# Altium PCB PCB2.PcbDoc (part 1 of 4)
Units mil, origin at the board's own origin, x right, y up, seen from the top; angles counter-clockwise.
Board outline 7170.03 x 5785.03 mil, 4 copper layers (Top Layer, GND, PWR, Bottom Layer), stack 22.378 mil thick; 348 components, 320 nets, 1937 pads, 429 vias.
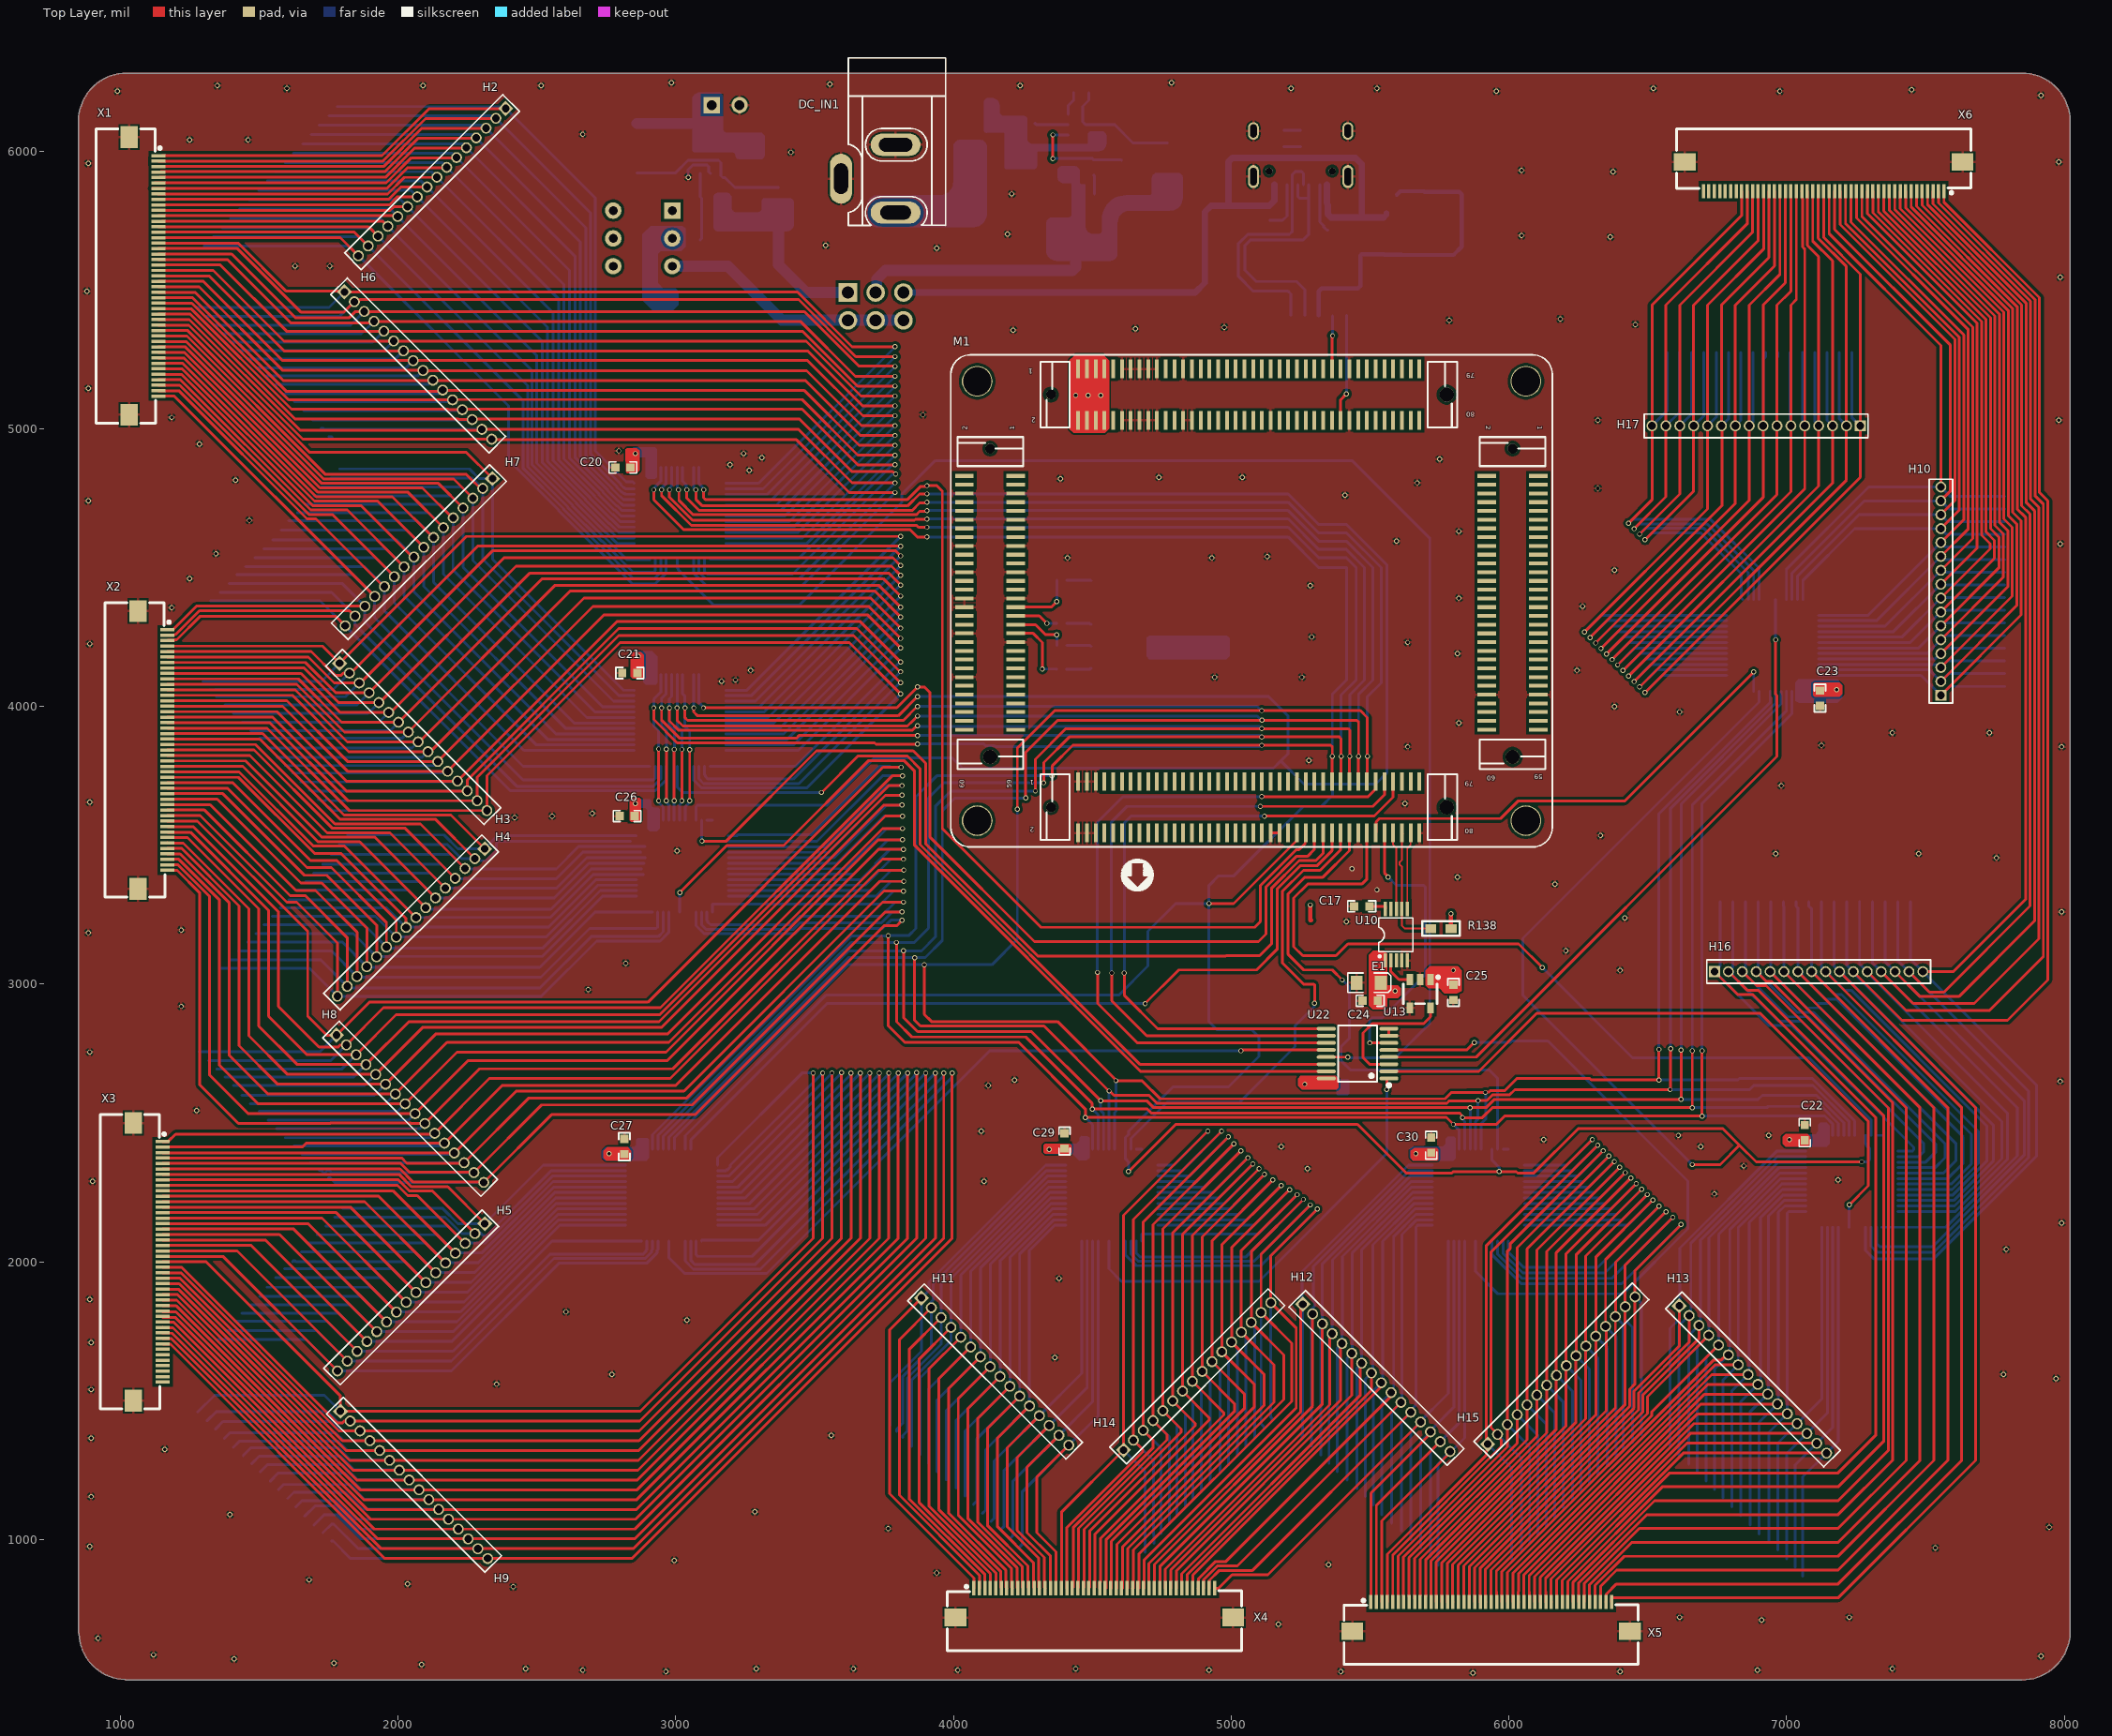
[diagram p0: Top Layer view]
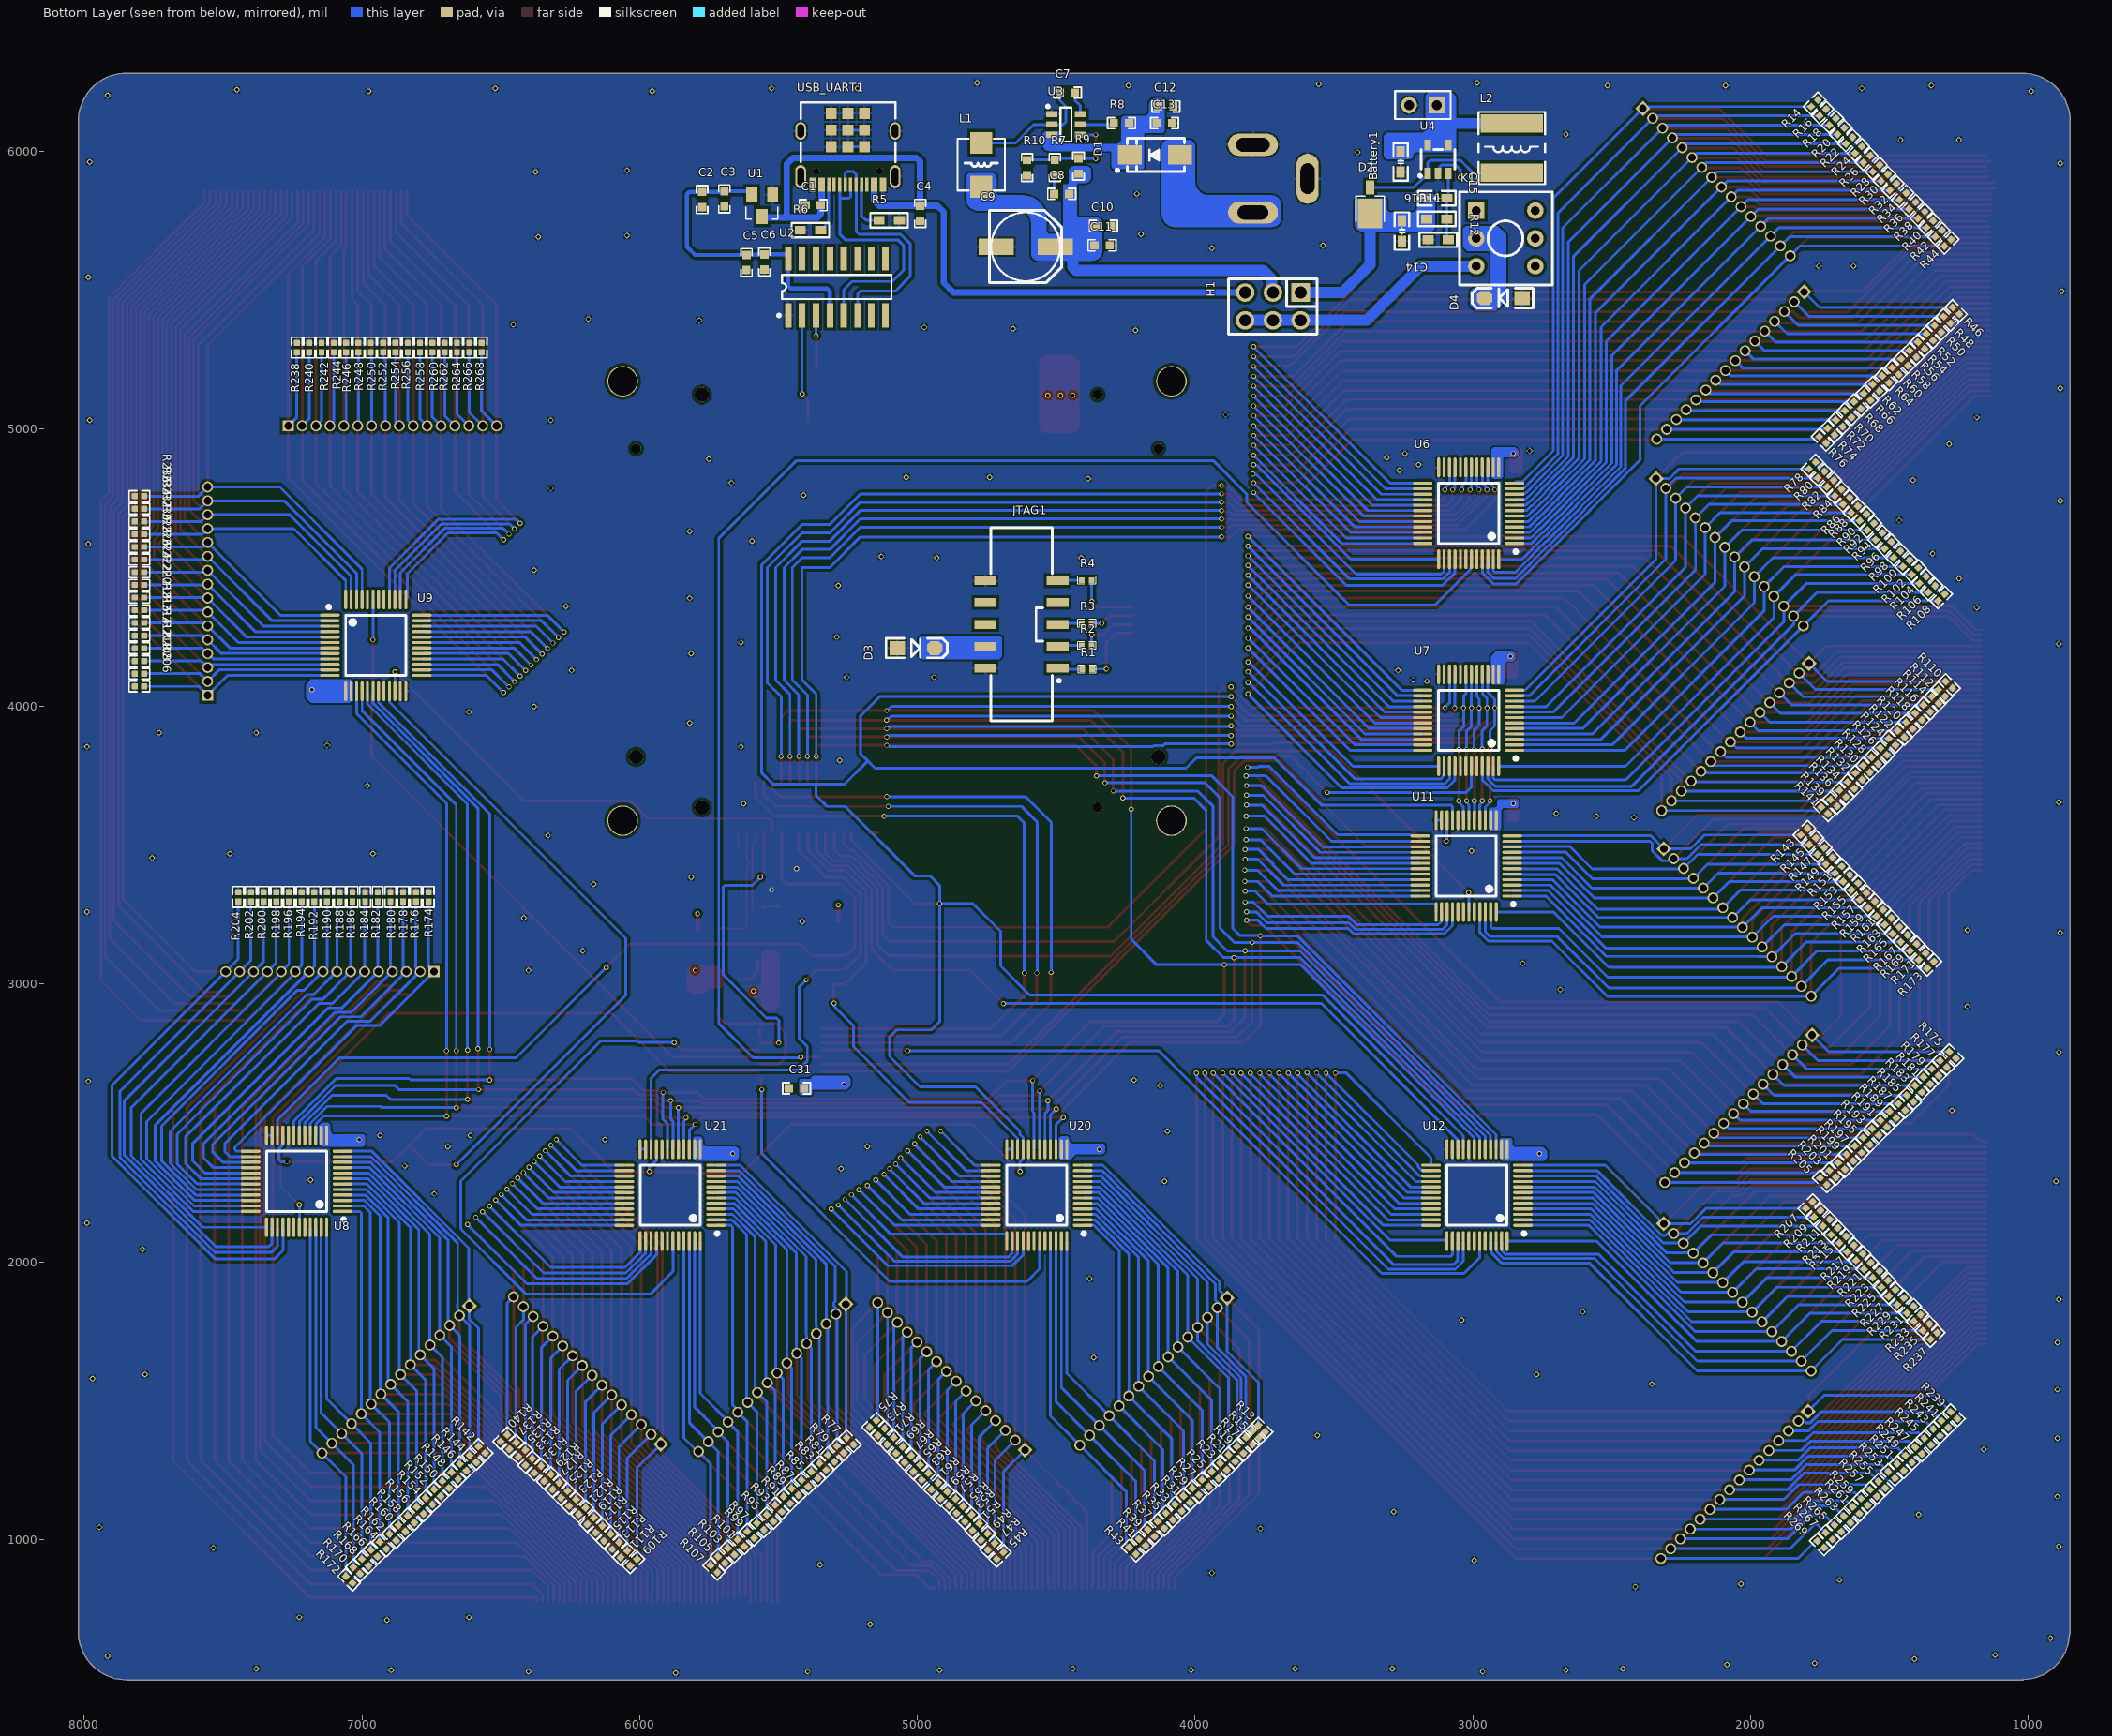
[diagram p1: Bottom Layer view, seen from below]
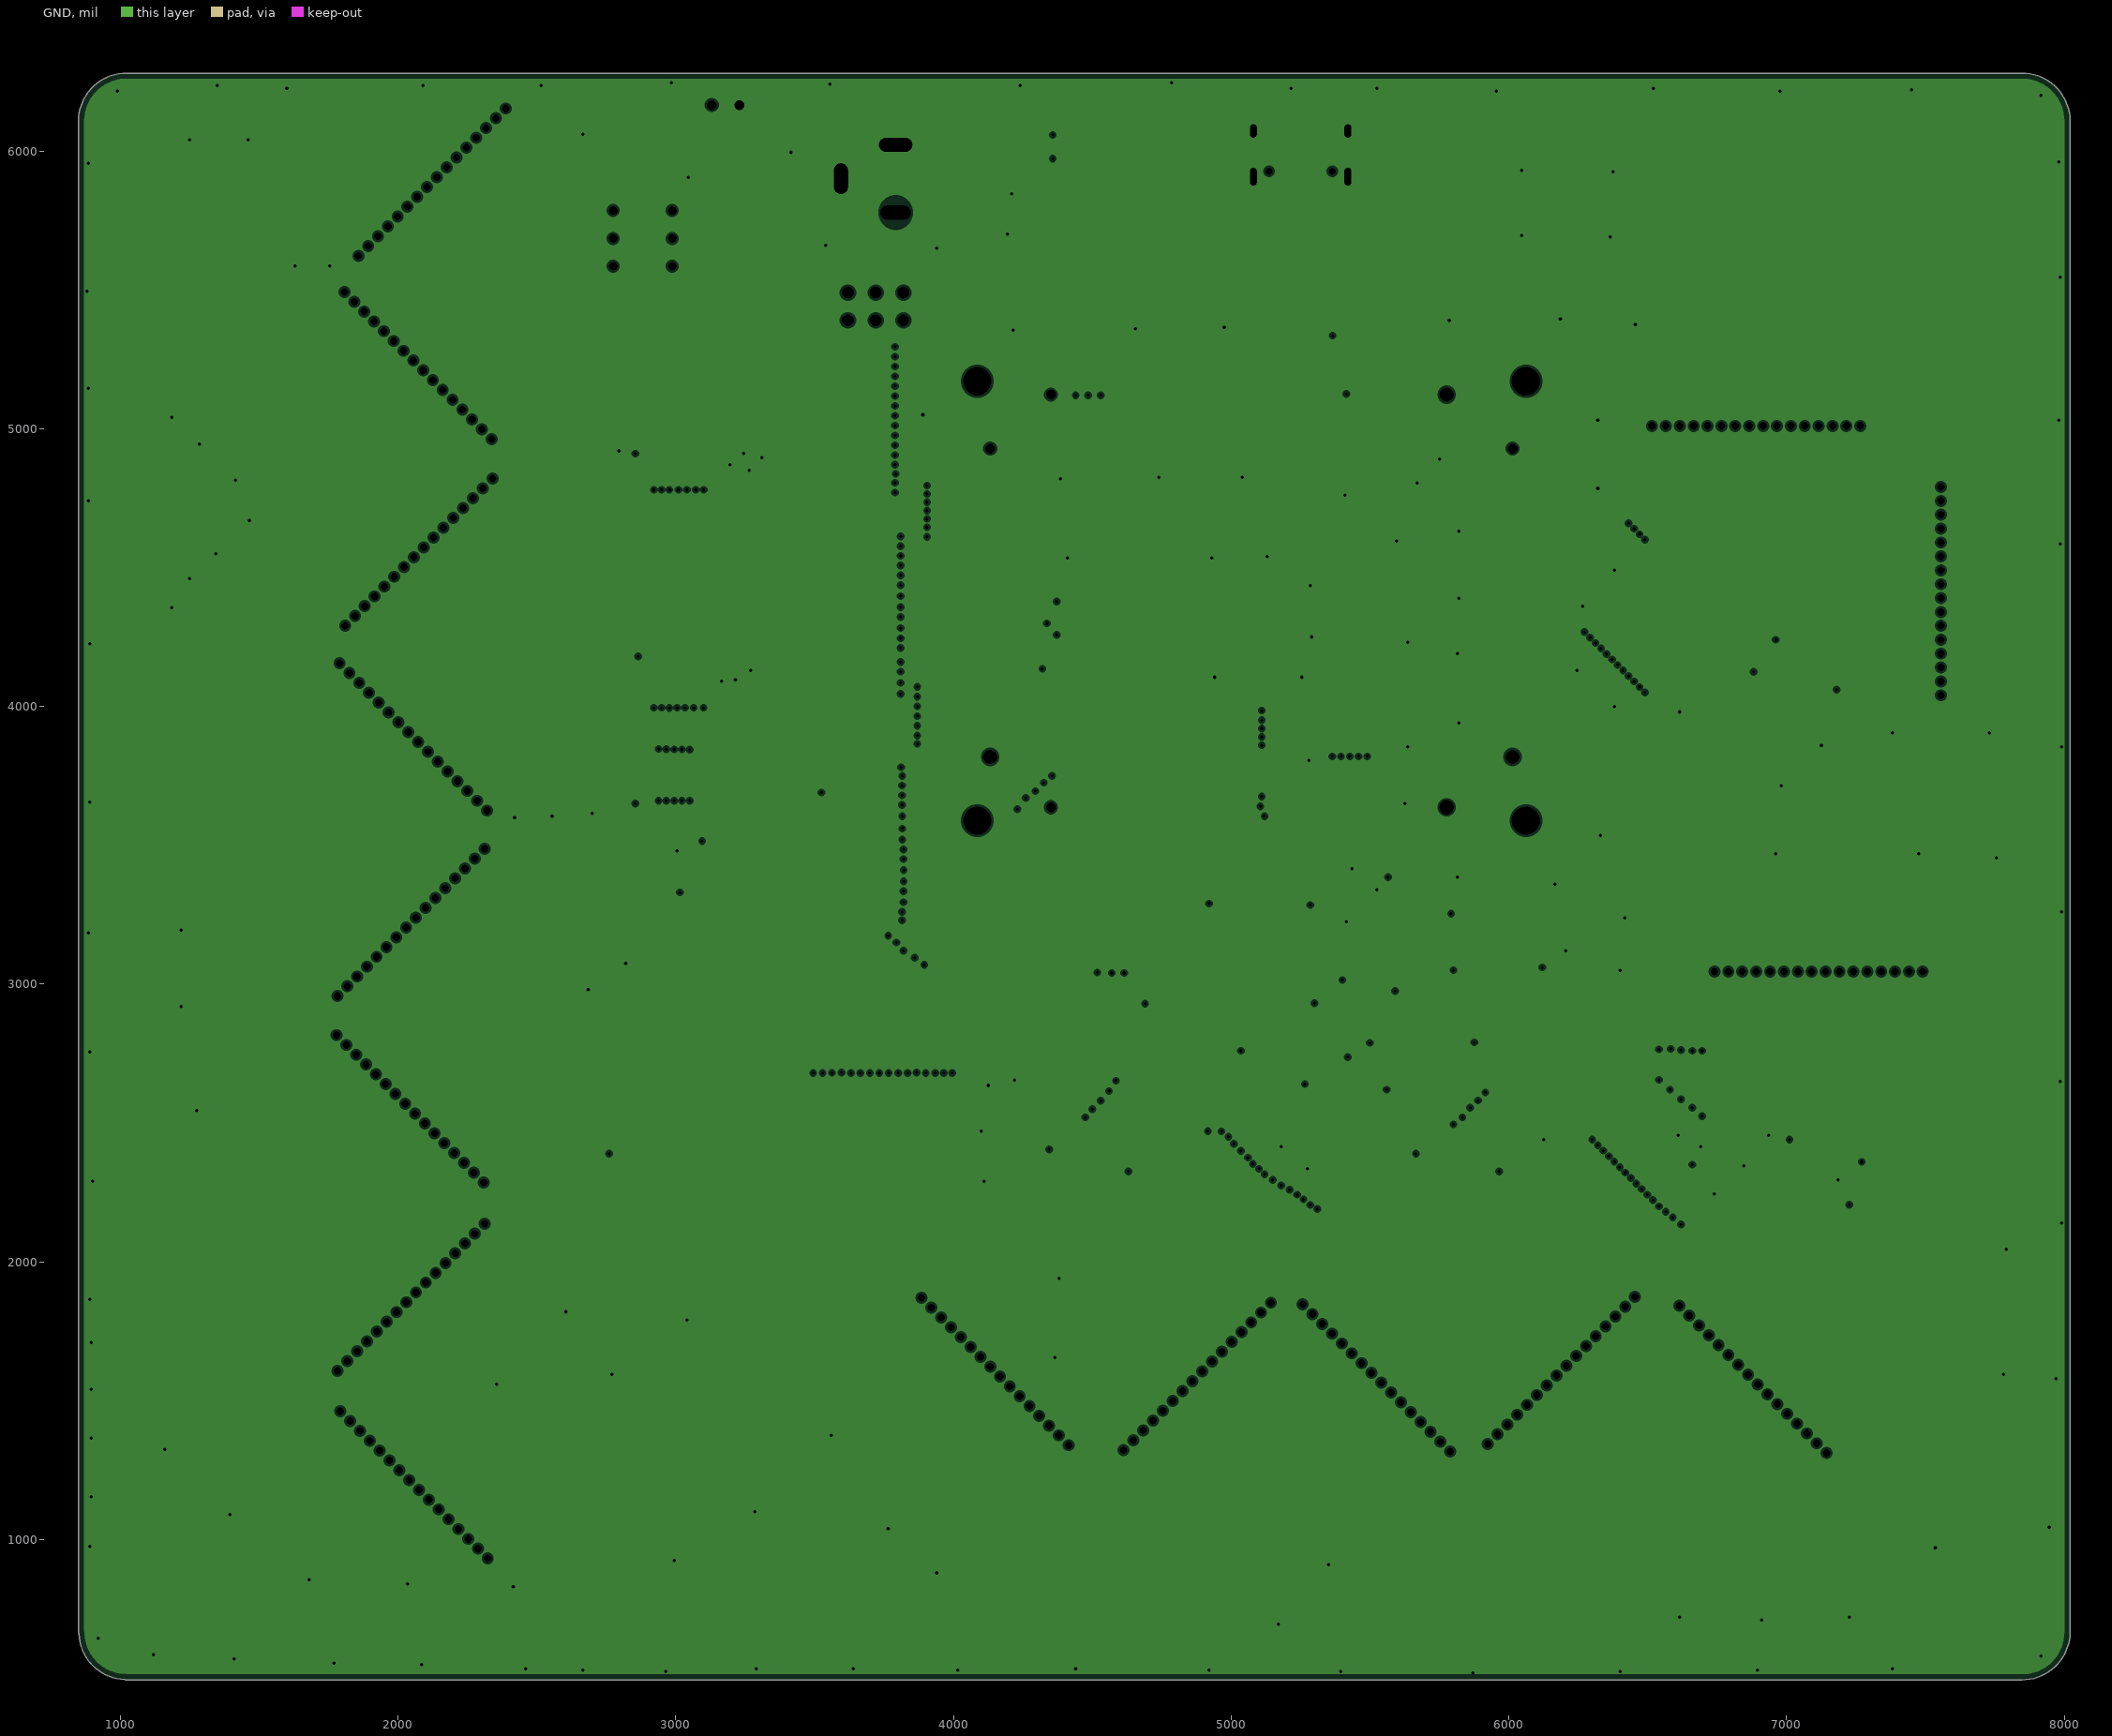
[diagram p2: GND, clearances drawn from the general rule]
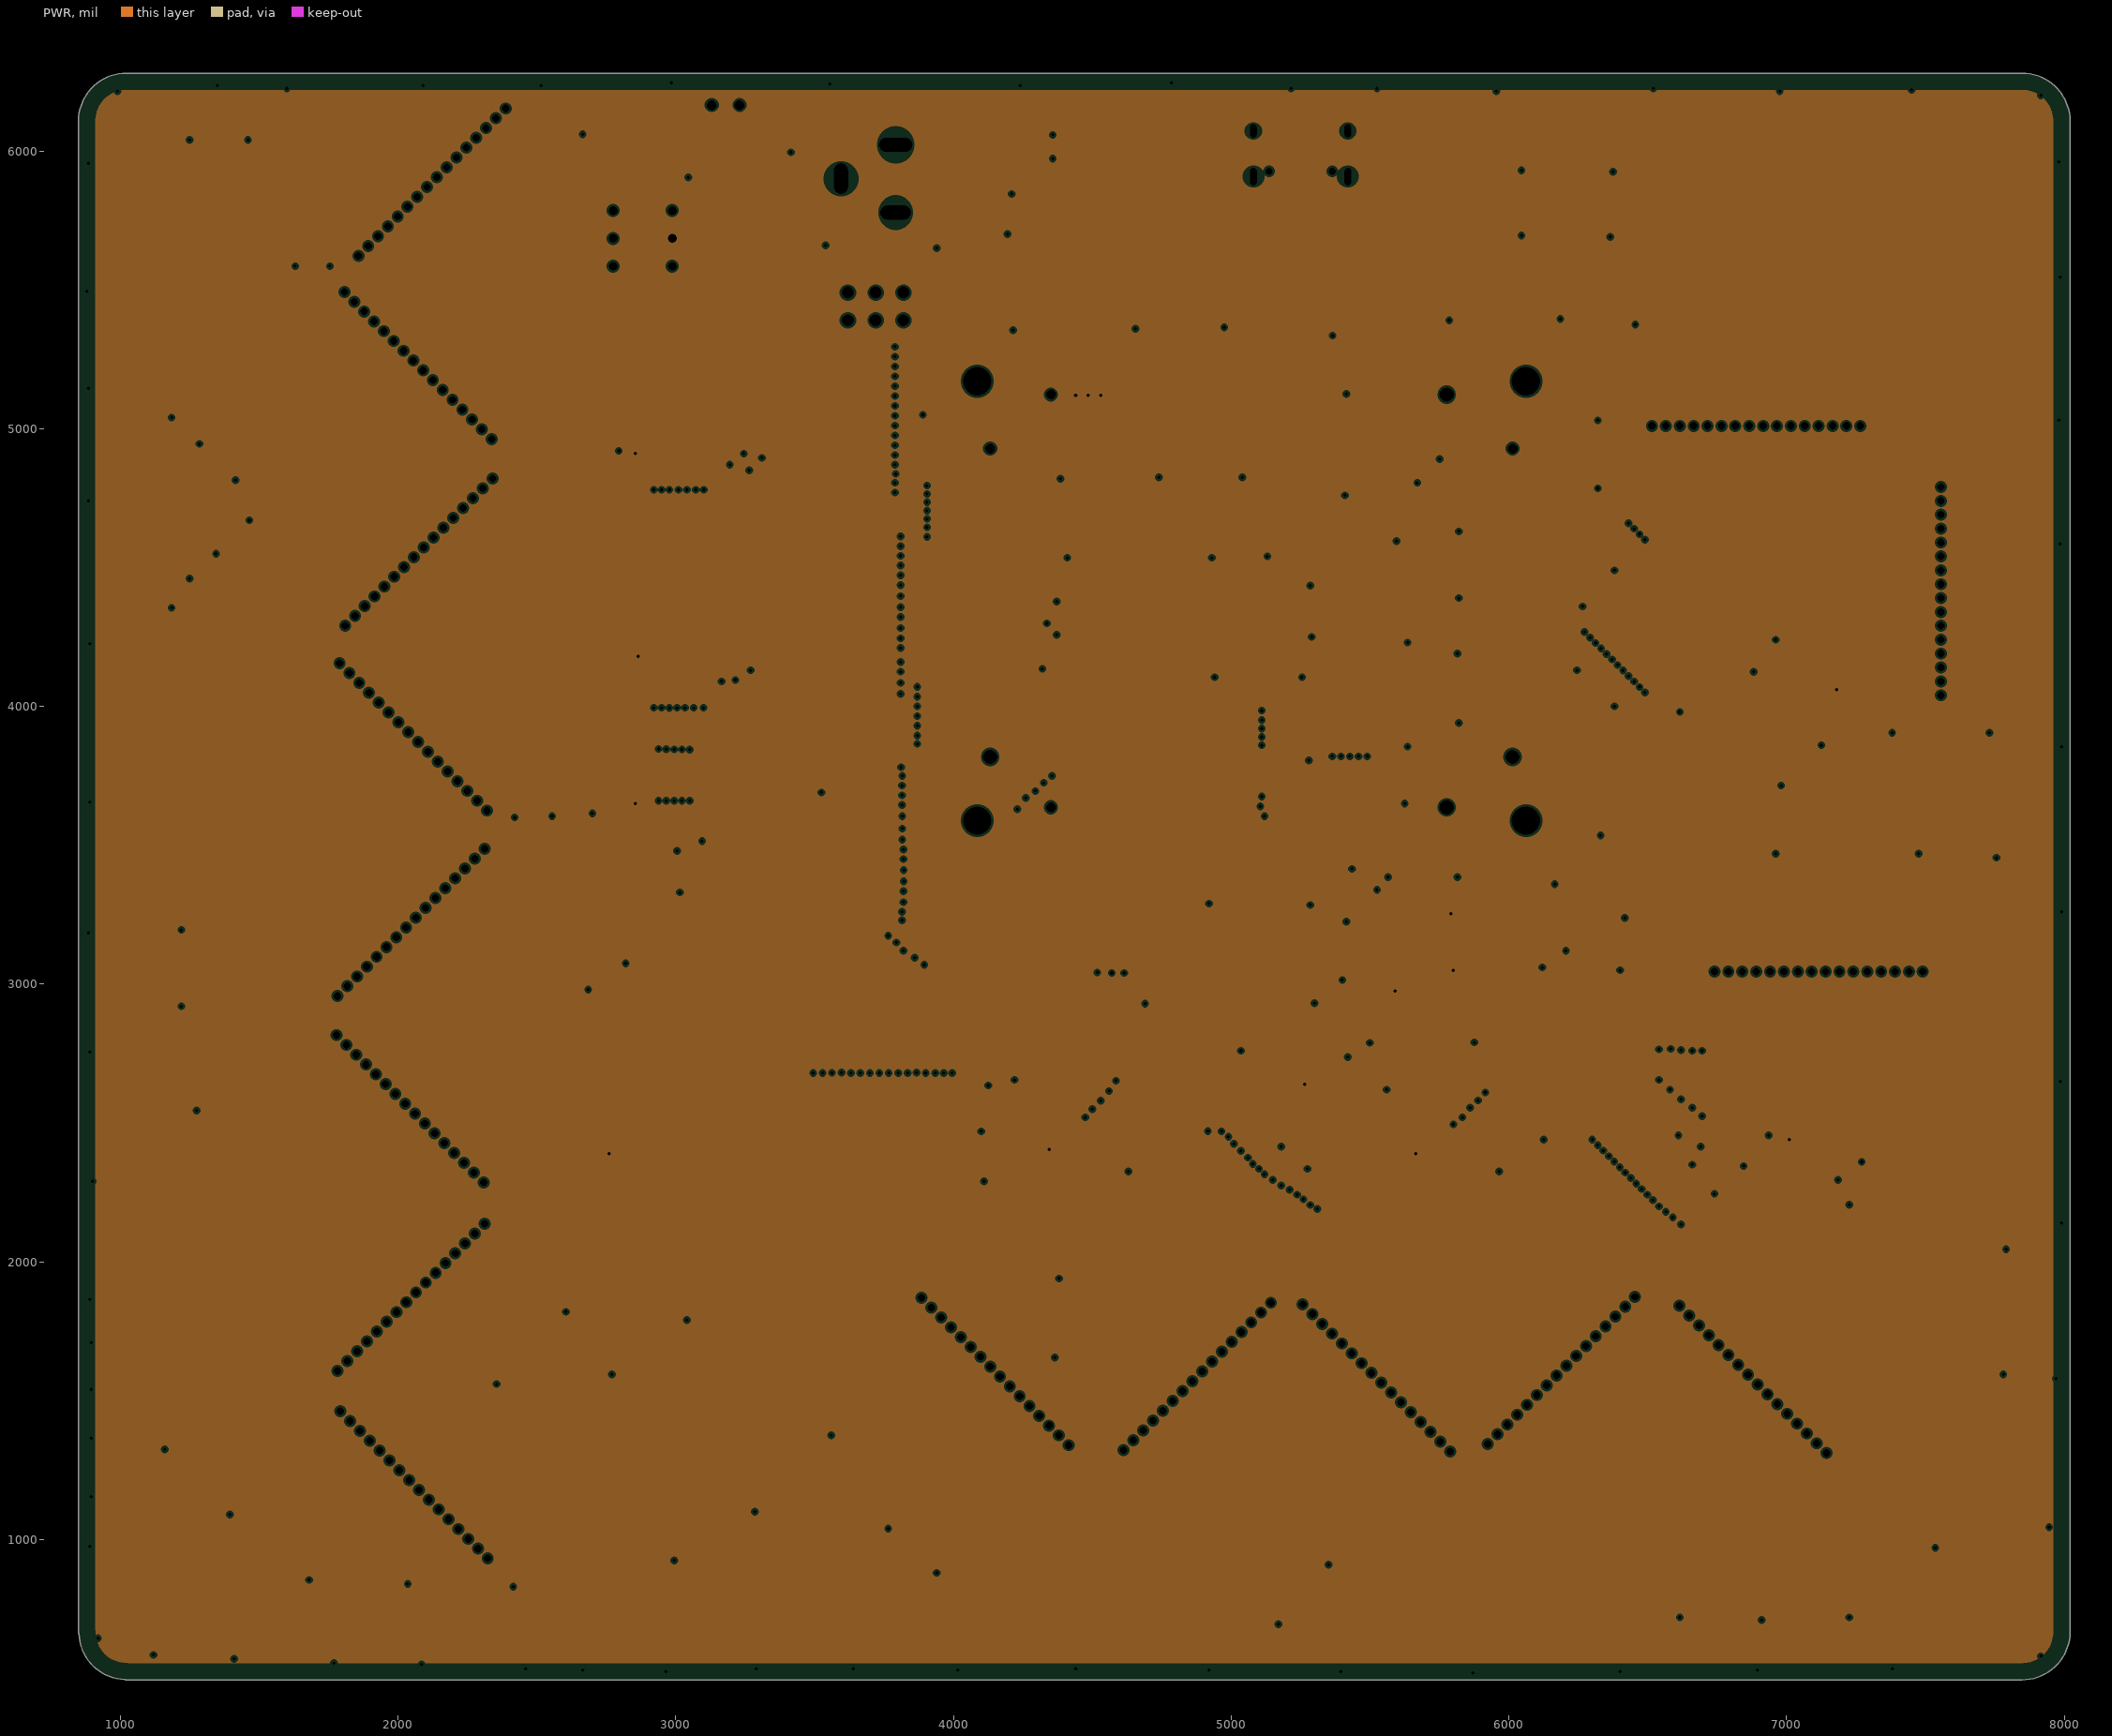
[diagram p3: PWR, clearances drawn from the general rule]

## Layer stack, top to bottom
Top Solder: solder mask 0.4, Solder Resist, Dk 3.5
Top Layer: signal copper 1.4
Dielectric 2: prepreg 2.8, PP-006, Dk 4.1
GND: plane copper 0.689, net GND
Dielectric 1: dielectric 12.6, FR-4, Dk 4.8
PWR: plane copper 0.689, net +5V
Dielectric 3: prepreg 2.8, PP-006, Dk 4.1
Bottom Layer: signal copper 1.4
Bottom Solder: solder mask 0.4, Solder Resist, Dk 3.5

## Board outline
851.39,661.21 ccw(c1021.33,666.33) 1016.21,496.39 ccw(c1021.33,505) 1021.33,494.99 7847.92,494.99 ccw(c7847.92,667.08) 8020.02,667.08 8020.02,6107.92 ccw(c7847.92,6107.92) 7847.92,6280.02 1022.08,6280.02 ccw(c1022.08,6107.92) 849.99,6107.92 849.99,666.33 ccw(c860,666.33)

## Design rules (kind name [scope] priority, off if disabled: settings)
Clearance [All] p1: gap=10 ignorepadtopadclearanceinfootprint=FALSE except(0: Arc-Hole Track-Hole SMDPad-Hole THPad-Hole Via-Hole Fill-Hole Poly-Hole Region-Hole Text-Hole; 6: Arc-Arc Arc-Track Arc-Region Track-Track Track-SMDPad Track-Region SMDPad-SMDPad SMDPad-Region THPad-THPad THPad-Region Via-Region Fill-Region Poly-Region Region-Region)
ComponentClearance [All] p1: gap=0 collisioncheckmode=3 verticalgap=0 showdistances=FALSE
MinimumSolderMaskSliver [All] p1: minsoldermaskwidth=4
PlaneClearance [All] p1: clearance=8
PlaneConnect [All] p1: planeconnectstyle=Relief reliefexpansion=18 reliefentries=4 reliefconductorwidth=10 reliefairgap=6
PolygonConnect [All] p1: connectstyle=Relief reliefconductorwidth=10 reliefentries=4 polygonreliefangle="90 Angle" airgapwidth=6
RoutingVias [All] p1: holewidth=12 width=18 viastyle="Through Hole" minholewidth=12 minwidth=18 maxholewidth=12 maxwidth=18
SilkToSilkClearance [All] p1: silktosilkclearance=0
SilkToSolderMaskClearance [IsPad] p1: minsilkscreentomaskgap=0 clearancetoexposedcopper=TRUE
SolderMaskExpansion [All] p1: expansion=4 istentingtop=FALSE
Width [All] p1: maxlimit=60 minlimit=6 preferedwidth=10
24 further rules are at their usual default settings.

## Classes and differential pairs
component class 底板电路1: C17 C20 C21 C22 C23 C24 C25 C26 C27 C29 C30 C31 E1 H2 H3 H4 H5 H6 H7 H8 H9 H10 H11 H12 H13 H14 H15 H16 H17 M1 R13 R14 R15 R16 R17 R18 R19 R20 R21 R22 R23 R24 R25 R26 R27 R28 R29 R30 R31 R32 R33 R34 R35 R36 R37 R38 R39 R40 R41 R42 R43 R44 R45 R46 R47 R48 R49 R50 R51 R52 R53 R54 R55 R56 R57 R58 R59 R60 R61 R62 R63 R64 R65 R66 R67 R68 R69 R70 R71 R72 R73 R74 R75 R76 R77 R78 R79 R80 R81 R82 R83 R84 R85 R86 R87 R88 R89 R90 R91 R92 R93 R94 R95 R96 R97 R98 R99 R100 R101 R102 R103 R104 R105 R106 R107 R108 R109 R110 R111 R112 R113 R114 R115 R116 R117 R118 R119 R120 R121 R122 R123 R124 R125 R126 R127 R128 R129 R130 R131 R132 R133 R134 R135 R136 R137 R138 R139 R140 R141 R142 R143 R144 R145 R146 R147 R148 R149 R150 R151 R152 R153 R154 R155 R156 R157 R158 R159 R160 R161 R162 R163 R164 R165 R166 R167 R168 R169 R170 R171 R172 R173 R174 R175 R176 R177 R178 R179 R180 R181 R182 R183 R184 R185 R186 R187 R188 R189 R190 R191 R192 R193 R194 R195 R196 R197 R198 R199 R200 R201 R202 R203 R204 R205 R206 R207 R208 R209 R210 R211 R212 R213 R214 R215 R216 R217 R218 R219 R220 R221 R222 R223 R224 R225 R226 R227 R228 R229 R230 R231 R232 R233 R234 R235 R236 R237 R238 R239 R240 R241 R242 R243 R244 R245 R246 R247 R248 R249 R250 R251 R252 R253 R254 R255 R256 R257 R258 R259 R260 R261 R262 R263 R264 R265 R266 R267 R268 R269 U6 U7 U8 U9 U10 U11 U12 U13 U20 U21 U22 X1 X2 X3 X4 X5 X6
component class 供电模块: Battery1 C1 C2 C3 C4 C5 C6 C7 C8 C9 C10 C11 C12 C13 C14 C15 C16 D1 D2 D3 D4 DC_IN1 H1 JTAG1 K1 L1 L2 R1 R2 R3 R4 R5 R6 R7 R8 R9 R10 R11 R12 U1 U2 U3 U4 USB_UART1

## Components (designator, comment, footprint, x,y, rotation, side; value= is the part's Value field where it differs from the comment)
Battery1 "Header 2" HDR1X2 3130,6165 r0 bottom
C1 "10uF" 0603P 5375,5805 r180 bottom
C2 "104" 0603P 5774.76,5824.83 r90 bottom
C3 "10uF" 0603P 5694.7,5827.33 r90 bottom
C4 "104" 0603P 4990,5775 r90 bottom
C5 "104" 0603P 5615.24,5598.37 r270 bottom
C6 "10uF" 0603P 5550.24,5600.37 r270 bottom
C7 "104" 0603P 4460,6210 r180 bottom
C8 "103" 0603P 4480,5845 r0 bottom
C9 "470uF" "CM D(6.3*5.4)" 4610,5655 r180 bottom
C10 "104" 0603P 4330,5730 r180 bottom
C11 "22uF" 0603P 4335,5660 r180 bottom
C12 "47uF/25V" 0603P 4105,6160 r0 bottom
C13 "104" 0603P 4110,6100 r0 bottom
C14 "4.7uF" "C 0603_M" 3255,5711.5 r270 bottom
C15 "4.7pF" "C 0603_M" 3130,5830 r180 bottom
C16 "4.7uF" "C 0603_M" 3260,5960 r270 bottom
C17 "0.1uF" 0603P 5470,3280 r0 top
C20 "0.1uF" 0603P 2810,4860 r180 top
C21 "0.1uF" 0603P 2835,4120 r180 top
C22 "0.1uF" 0603P 7065,2465 r90 top
C23 "0.1uF" 0603P 7120,4030 r270 top
C24 "0.1uF" 0603P 5500,2940 r0 top
C25 "0.1uF" 0603P 5800,2970 r90 top
C26 "0.1uF" 0603P 2825,3605 r180 top
C27 "0.1uF" 0603P 2815,2415 r90 top
C29 "0.1uF" 0603P 4400,2435 r90 top
C30 "0.1uF" 0603P 5720,2420 r90 top
C31 "0.1uF" 0603P 5435,2625 r0 bottom
D1 "SS24" SMA 4145,5985 r0 bottom
D2 "MBRM130LT1G" DIO-SMD_L2.0-W1.9-LS3.8-RD 3370.03,5821.66 r90 bottom
D3 "SMFJ3.3CA" SOD-123 5005,4210 r180 bottom
D4 "SMFJ5.0CA" SOD-123 2890,5470 r0 bottom
DC_IN1 "POWER" DC10B 3791.85,5777.95 r90 top
E1 "10uF" "CD S(2012)" 5495,3005 r180 top
H1 "PZ254V-12-6P" HDR-TH_6P-P2.54-V-M-R2-C3-S2.54 3720,5440 r0 bottom
H2 "BX-PZ1.27-1-16PZZ" HDR-TH_16P-P1.27-V-M 2122.68,5887.68 r225 top
H3 "BX-PZ1.27-1-16PZZ" HDR-TH_16P-P1.27-V-M 2075.19,4555.19 r225 top
H4 "BX-PZ1.27-1-16PZZ" HDR-TH_16P-P1.27-V-M 2046.97,3221.97 r225 top
H5 "BX-PZ1.27-1-16PZZ" HDR-TH_16P-P1.27-V-M 2047.32,1872.32 r225 top
H6 "BX-PZ1.27-1-16PZZ" HDR-TH_16P-P1.27-V-M 2072.68,5227.32 r315 top
H7 "BX-PZ1.27-1-16PZZ" HDR-TH_16P-P1.27-V-M 2055,3890 r315 top
H8 "BX-PZ1.27-1-16PZZ" HDR-TH_16P-P1.27-V-M 2043.74,2551.26 r315 top
H9 "BX-PZ1.27-1-16PZZ" HDR-TH_16P-P1.27-V-M 2058.03,1196.97 r315 top
H10 "BX-PZ1.27-1-16PZZ" HDR-TH_16P-P1.27-V-M 7555,4415 r90 top
H11 "BX-PZ1.27-1-16PZZ" HDR-TH_16P-P1.27-V-M 4150,1605 r315 top
H12 "BX-PZ1.27-1-16PZZ" HDR-TH_16P-P1.27-V-M 5522.68,1582.32 r315 top
H13 "BX-PZ1.27-1-16PZZ" HDR-TH_16P-P1.27-V-M 6878.39,1576.61 r315 top
H14 "BX-PZ1.27-1-16PZZ" HDR-TH_16P-P1.27-V-M 4877.68,1587.68 r45 top
H15 "BX-PZ1.27-1-16PZZ" HDR-TH_16P-P1.27-V-M 6188.74,1608.74 r45 top
H16 "BX-PZ1.27-1-16PZZ" HDR-TH_16P-P1.27-V-M 7115,3045 r0 top
H17 "BX-PZ1.27-1-16PZZ" HDR-TH_16P-P1.27-V-M 6890,5010 r180 top
JTAG1 "JTAG-10-FPGA" HDR-IDC-SMD_10PIN-V-ROW2-COL5-PITCH2.00 4625,4295 r90 bottom
K1 "BUTTON" BTN8.5*8.5 2987.6,5785 r180 bottom
L1 "4.7uH" L-SMD-0420 4770,5950 r270 bottom
L2 "2.2uH" NR6028 2860,6010 r270 bottom
M1 "A7_CORE" ARTIX7_Core 6061.22,5170.67 r180 top
R1 "33" 0402 4389,4135 r0 bottom
R2 "33" 0402 4390,4220 r0 bottom
R3 "33" 0402 4390,4300 r0 bottom
R4 "33" 0402 4390,4455 r0 bottom
R5 "5.1K" "R 0603_M" 5101.5,5750 r180 bottom
R6 "5.1K" "R 0603_M" 5385,5715 r0 bottom
R7 "1K" 0603P 4505,5940 r90 bottom
R8 "100K" 0603P 4265,6100 r0 bottom
R9 "82.5K" 0603P 4420,5945 r90 bottom
R10 "15K" 0603P 4605,5940 r270 bottom
R11 "1M" "R 0603_M" 3130,5755 r0 bottom
R12 "330K" "R 0603_M" 3125,5680 r180 bottom
R13 "10kΩ" R0402 3760,1400 r45 bottom
R14 "10kΩ" R0402 1769.91,6171.48 r315 bottom
R15 "10kΩ" R0402 3782.95,1377.95 r45 bottom
R16 "10kΩ" R0402 1739.91,6137.98 r315 bottom
R17 "10kΩ" R0402 3805,1355 r45 bottom
R18 "10kΩ" R0402 1704.91,6104.49 r315 bottom
R19 "10kΩ" R0402 3837.95,1322.95 r45 bottom
R20 "10kΩ" R0402 1674.91,6071 r315 bottom
R21 "10kΩ" R0402 3867.95,1292.95 r45 bottom
R22 "10kΩ" R0402 1644.91,6037.5 r315 bottom
R23 "10kΩ" R0402 3897.95,1262.95 r45 bottom
R24 "10kΩ" R0402 1611.96,6004.01 r315 bottom
R25 "10kΩ" R0402 3927.95,1232.95 r45 bottom
R26 "10kΩ" R0402 1581.96,5970.51 r315 bottom
R27 "10kΩ" R0402 3962.95,1202.95 r45 bottom
R28 "10kΩ" R0402 1547.86,5937.02 r315 bottom
R29 "10kΩ" R0402 3997.95,1172.95 r45 bottom
R30 "10kΩ" R0402 1517.86,5903.52 r315 bottom
R31 "10kΩ" R0402 4030,1145 r45 bottom
R32 "10kΩ" R0402 1486.96,5870.03 r315 bottom
R33 "10kΩ" R0402 4060,1115 r45 bottom
R34 "10kΩ" R0402 1451.96,5836.54 r315 bottom
R35 "10kΩ" R0402 4092.95,1082.95 r45 bottom
R36 "10kΩ" R0402 1418.04,5803.04 r315 bottom
R37 "10kΩ" R0402 4122.95,1052.95 r45 bottom
R38 "10kΩ" R0402 1385.09,5769.55 r315 bottom
R39 "10kΩ" R0402 4157.95,1022.95 r45 bottom
R40 "10kΩ" R0402 1355.09,5736.05 r315 bottom
R41 "10kΩ" R0402 4190,990 r45 bottom
R42 "10kΩ" R0402 1323.04,5702.56 r315 bottom
R43 "10kΩ" R0402 4225,960 r45 bottom
R44 "10kΩ" R0402 1290.09,5669.06 r315 bottom
R45 "10kΩ" R0402 4701.96,941.96 r135 bottom
R46 "10kΩ" R0402 1260.54,5424.47 r45 bottom
R47 "10kΩ" R0402 4734.01,974.91 r135 bottom
R48 "10kΩ" R0402 1292.59,5391.51 r45 bottom
R49 "10kΩ" R0402 4759.01,1009.91 r135 bottom
R50 "10kΩ" R0402 1325.54,5359.47 r45 bottom
R51 "10kΩ" R0402 4789.01,1044.91 r135 bottom
R52 "10kΩ" R0402 1355.54,5329.47 r45 bottom
R53 "10kΩ" R0402 4816.96,1076.96 r135 bottom
R54 "10kΩ" R0402 1385.54,5299.47 r45 bottom
R55 "10kΩ" R0402 4846.96,1106.96 r135 bottom
R56 "10kΩ" R0402 1415.54,5269.47 r45 bottom
R57 "10kΩ" R0402 4874.01,1134.91 r135 bottom
R58 "10kΩ" R0402 1445.54,5239.47 r45 bottom
R59 "10kΩ" R0402 4904.01,1159.91 r135 bottom
R60 "10kΩ" R0402 1478.5,5207.42 r45 bottom
R61 "10kΩ" R0402 4936.96,1191.96 r135 bottom
R62 "10kΩ" R0402 1513.5,5177.42 r45 bottom
R63 "10kΩ" R0402 4971.96,1226.96 r135 bottom
R64 "10kΩ" R0402 1548.5,5147.42 r45 bottom
R65 "10kΩ" R0402 5001.96,1256.96 r135 bottom
R66 "10kΩ" R0402 1580.54,5114.47 r45 bottom
R67 "10kΩ" R0402 5034.01,1289.91 r135 bottom
R68 "10kΩ" R0402 1615.54,5084.47 r45 bottom
R69 "10kΩ" R0402 5064.6,1322.12 r135 bottom
R70 "10kΩ" R0402 1648.5,5052.42 r45 bottom
R71 "10kΩ" R0402 5096.65,1355.07 r135 bottom
R72 "10kΩ" R0402 1680.54,5019.47 r45 bottom
R73 "10kΩ" R0402 5129.6,1387.12 r135 bottom
R74 "10kΩ" R0402 1710.54,4989.47 r45 bottom
R75 "10kΩ" R0402 5159.6,1417.12 r135 bottom
R76 "10kΩ" R0402 1740.54,4959.47 r45 bottom
R77 "10kΩ" R0402 5242.23,1354.47 r45 bottom
R78 "10kΩ" R0402 1777.95,4867.05 r315 bottom
R79 "10kΩ" R0402 5277.23,1324.47 r45 bottom
R80 "10kΩ" R0402 1745.9,4834.1 r315 bottom
R81 "10kΩ" R0402 5310.18,1292.42 r45 bottom
R82 "10kΩ" R0402 1712.95,4802.05 r315 bottom
R83 "10kΩ" R0402 5340.18,1262.42 r45 bottom
R84 "10kΩ" R0402 1685,4770 r315 bottom
R85 "10kΩ" R0402 5370.18,1232.42 r45 bottom
R86 "10kΩ" R0402 1655,4740 r315 bottom
R87 "10kΩ" R0402 5405.18,1202.42 r45 bottom
R88 "10kΩ" R0402 1625.9,4709.1 r315 bottom
R89 "10kΩ" R0402 5440.18,1172.42 r45 bottom
R90 "10kΩ" R0402 1595,4680 r315 bottom
R91 "10kΩ" R0402 5470.18,1142.42 r45 bottom
R92 "10kΩ" R0402 1567.95,4647.05 r315 bottom
R93 "10kΩ" R0402 5500.18,1112.42 r45 bottom
R94 "10kΩ" R0402 1537.95,4612.05 r315 bottom
R95 "10kΩ" R0402 5530.18,1077.42 r45 bottom
R96 "10kΩ" R0402 1505,4580 r315 bottom
R97 "10kΩ" R0402 5565.18,1047.42 r45 bottom
R98 "10kΩ" R0402 1472.95,4547.05 r315 bottom
R99 "10kΩ" R0402 5600.18,1017.42 r45 bottom
R100 "10kΩ" R0402 1440,4515 r315 bottom
R101 "10kΩ" R0402 5635.18,987.42 r45 bottom
R102 "10kΩ" R0402 1407.95,4487.05 r315 bottom
R103 "10kΩ" R0402 5670.18,957.42 r45 bottom
R104 "10kΩ" R0402 1380,4455 r315 bottom
R105 "10kΩ" R0402 5705.18,927.42 r45 bottom
R106 "10kΩ" R0402 1347.95,4422.05 r315 bottom
R107 "10kΩ" R0402 5732.23,894.47 r45 bottom
R108 "10kΩ" R0402 1312.95,4392.05 r315 bottom
R109 "10kΩ" R0402 6021.49,917.43 r135 bottom
R110 "10kΩ" R0402 1285.53,4077.77 r45 bottom
R111 "10kΩ" R0402 6056.49,947.43 r135 bottom
R112 "10kΩ" R0402 1312.26,4048.16 r45 bottom
R113 "10kΩ" R0402 6086.49,977.43 r135 bottom
R114 "10kΩ" R0402 1335.53,4022.77 r45 bottom
R115 "10kΩ" R0402 6116.49,1007.43 r135 bottom
R116 "10kΩ" R0402 1365.53,3992.77 r45 bottom
R117 "10kΩ" R0402 6146.49,1037.43 r135 bottom
R118 "10kΩ" R0402 1395.53,3962.77 r45 bottom
R119 "10kΩ" R0402 6176.49,1067.43 r135 bottom
R120 "10kΩ" R0402 1428.48,3930.72 r45 bottom
R121 "10kΩ" R0402 6206.49,1102.43 r135 bottom
R122 "10kΩ" R0402 1458.48,3900.72 r45 bottom
R123 "10kΩ" R0402 6241.49,1132.43 r135 bottom
R124 "10kΩ" R0402 1490.53,3872.77 r45 bottom
R125 "10kΩ" R0402 6271.49,1162.43 r135 bottom
R126 "10kΩ" R0402 1520.53,3837.77 r45 bottom
R127 "10kΩ" R0402 6301.49,1192.43 r135 bottom
R128 "10kΩ" R0402 1552.58,3804.82 r45 bottom
R129 "10kΩ" R0402 6331.49,1222.43 r135 bottom
R130 "10kΩ" R0402 1582.58,3774.82 r45 bottom
R131 "10kΩ" R0402 6366.49,1252.43 r135 bottom
R132 "10kΩ" R0402 1610.53,3747.77 r45 bottom
R133 "10kΩ" R0402 6398.54,1280.38 r135 bottom
R134 "10kΩ" R0402 1638.48,3715.72 r45 bottom
R135 "10kΩ" R0402 6423.54,1310.38 r135 bottom
R136 "10kΩ" R0402 1668.48,3685.72 r45 bottom
R137 "10kΩ" R0402 6456.49,1337.43 r135 bottom
R138 "10K" "R 0603_M" 5755,3200 r0 top
R139 "10kΩ" R0402 1700.53,3652.77 r45 bottom
R140 "10kΩ" R0402 6488.54,1365.38 r135 bottom
R141 "10kΩ" R0402 1733.48,3625.72 r45 bottom
R142 "10kΩ" R0402 6568.16,1323.2 r45 bottom
R143 "10kΩ" R0402 1807.02,3549.06 r315 bottom
R144 "10kΩ" R0402 6600.21,1290.24 r45 bottom
R145 "10kΩ" R0402 1777.02,3514.06 r315 bottom
R146 "10kΩ" R0402 6635.21,1260.24 r45 bottom
R147 "10kΩ" R0402 1747.02,3479.06 r315 bottom
R148 "10kΩ" R0402 6665.21,1230.24 r45 bottom
R149 "10kΩ" R0402 1717.02,3444.06 r315 bottom
R150 "10kΩ" R0402 6698.16,1198.2 r45 bottom
R151 "10kΩ" R0402 1684.07,3412.01 r315 bottom
R152 "10kΩ" R0402 6728.16,1168.2 r45 bottom
R153 "10kΩ" R0402 1654.97,3381.11 r315 bottom
R154 "10kΩ" R0402 6758.16,1138.2 r45 bottom
R155 "10kΩ" R0402 1624.97,3351.11 r315 bottom
R156 "10kΩ" R0402 6790.21,1105.24 r45 bottom
R157 "10kΩ" R0402 1594.97,3316.11 r315 bottom
R158 "10kΩ" R0402 6823.16,1073.2 r45 bottom
R159 "10kΩ" R0402 1564.97,3286.11 r315 bottom
R160 "10kΩ" R0402 6855.81,1040.81 r45 bottom
R161 "10kΩ" R0402 1534.97,3256.11 r315 bottom
R162 "10kΩ" R0402 6888.76,1008.76 r45 bottom
R163 "10kΩ" R0402 1504.97,3226.11 r315 bottom
R164 "10kΩ" R0402 6923.76,978.76 r45 bottom
R165 "10kΩ" R0402 1477.02,3194.06 r315 bottom
R166 "10kΩ" R0402 6955.81,950.81 r45 bottom
R167 "10kΩ" R0402 1447.02,3164.06 r315 bottom
R168 "10kΩ" R0402 6987.86,917.86 r45 bottom
R169 "10kΩ" R0402 1414.07,3132.01 r315 bottom
R170 "10kΩ" R0402 7018.76,888.76 r45 bottom
R171 "10kΩ" R0402 1382.02,3099.06 r315 bottom
R172 "10kΩ" R0402 7045.81,855.81 r45 bottom
R173 "10kΩ" R0402 1352.02,3069.06 r315 bottom
R174 "10kΩ" R0402 6759.84,3313.91 r270 bottom
R175 "10kΩ" R0402 1272.64,2744.84 r45 bottom
R176 "10kΩ" R0402 6805.53,3313.91 r270 bottom
R177 "10kΩ" R0402 1305.6,2712.79 r45 bottom
R178 "10kΩ" R0402 6851.22,3313.91 r270 bottom
R179 "10kΩ" R0402 1335.6,2682.79 r45 bottom
R180 "10kΩ" R0402 6896.91,3313.91 r270 bottom
R181 "10kΩ" R0402 1365.6,2652.79 r45 bottom
R182 "10kΩ" R0402 6942.6,3313.91 r270 bottom
R183 "10kΩ" R0402 1395.6,2622.79 r45 bottom
R184 "10kΩ" R0402 6988.3,3313.91 r270 bottom
R185 "10kΩ" R0402 1425.6,2587.79 r45 bottom
R186 "10kΩ" R0402 7033.99,3313.91 r270 bottom
R187 "10kΩ" R0402 1455.6,2557.79 r45 bottom
R188 "10kΩ" R0402 7079.68,3313.91 r270 bottom
R189 "10kΩ" R0402 1487.64,2529.84 r45 bottom
R190 "10kΩ" R0402 7125.37,3313.91 r270 bottom
R191 "10kΩ" R0402 1520.6,2497.79 r45 bottom
R192 "10kΩ" R0402 7171.06,3313.91 r270 bottom
R193 "10kΩ" R0402 1550.6,2467.79 r45 bottom
R194 "10kΩ" R0402 7216.75,3313.91 r270 bottom
R195 "10kΩ" R0402 1582.64,2434.84 r45 bottom
R196 "10kΩ" R0402 7262.44,3313.91 r270 bottom
R197 "10kΩ" R0402 1612.64,2404.84 r45 bottom
R198 "10kΩ" R0402 7308.14,3313.91 r270 bottom
R199 "10kΩ" R0402 1642.64,2374.84 r45 bottom
R200 "10kΩ" R0402 7353.83,3313.91 r270 bottom
R201 "10kΩ" R0402 1672.64,2344.84 r45 bottom
R202 "10kΩ" R0402 7399.52,3313.91 r270 bottom
R203 "10kΩ" R0402 1704.69,2316.89 r45 bottom
R204 "10kΩ" R0402 7445.21,3313.91 r270 bottom
R205 "10kΩ" R0402 1737.64,2289.84 r45 bottom
R206 "10kΩ" R0402 7801.09,4072.04 r180 bottom
R207 "10kΩ" R0402 1789.16,2204.41 r315 bottom
R208 "10kΩ" R0402 7801.09,4117.7 r180 bottom
R209 "10kΩ" R0402 1760.16,2172.64 r315 bottom
R210 "10kΩ" R0402 7801.09,4163.37 r180 bottom
R211 "10kΩ" R0402 1727.21,2140.6 r315 bottom
R212 "10kΩ" R0402 7801.09,4209.04 r180 bottom
R213 "10kΩ" R0402 1698.11,2109.69 r315 bottom
R214 "10kΩ" R0402 7801.09,4254.7 r180 bottom
R215 "10kΩ" R0402 1668.11,2079.69 r315 bottom
R216 "10kΩ" R0402 7801.09,4300.37 r180 bottom
R217 "10kΩ" R0402 1640.16,2047.64 r315 bottom
R218 "10kΩ" R0402 7801.09,4346.04 r180 bottom
R219 "10kΩ" R0402 1607.95,2017.05 r315 bottom
R220 "10kΩ" R0402 7801.09,4391.7 r180 bottom
R221 "10kΩ" R0402 1580,1985 r315 bottom
R222 "10kΩ" R0402 7801.09,4437.37 r180 bottom
R223 "10kΩ" R0402 1548.11,1954.69 r315 bottom
R224 "10kΩ" R0402 7801.09,4483.04 r180 bottom
R225 "10kΩ" R0402 1517.21,1920.6 r315 bottom
R226 "10kΩ" R0402 7801.09,4528.7 r180 bottom
R227 "10kΩ" R0402 1490.16,1887.64 r315 bottom
R228 "10kΩ" R0402 7801.09,4574.37 r180 bottom
R229 "10kΩ" R0402 1460.16,1857.64 r315 bottom
R230 "10kΩ" R0402 7801.09,4620.04 r180 bottom
R231 "10kΩ" R0402 1425.16,1827.64 r315 bottom
R232 "10kΩ" R0402 7801.09,4665.7 r180 bottom
R233 "10kΩ" R0402 1400.16,1797.64 r315 bottom
R234 "10kΩ" R0402 7801.09,4711.37 r180 bottom
R235 "10kΩ" R0402 1368.11,1764.69 r315 bottom
R236 "10kΩ" R0402 7801.09,4757.04 r180 bottom
R237 "10kΩ" R0402 1340.16,1732.64 r315 bottom
R238 "10kΩ" R0402 7233.96,5291.89 r270 bottom
R239 "10kΩ" R0402 1267.61,1447.64 r45 bottom
R240 "10kΩ" R0402 7189.63,5291.89 r270 bottom
R241 "10kΩ" R0402 1300.56,1415.6 r45 bottom
R242 "10kΩ" R0402 7145.3,5291.89 r270 bottom
R243 "10kΩ" R0402 1330.56,1385.6 r45 bottom
R244 "10kΩ" R0402 7100.96,5291.89 r270 bottom
R245 "10kΩ" R0402 1362.61,1352.64 r45 bottom
R246 "10kΩ" R0402 7056.63,5291.89 r270 bottom
R247 "10kΩ" R0402 1395.56,1320.6 r45 bottom
R248 "10kΩ" R0402 7012.3,5291.89 r270 bottom
R249 "10kΩ" R0402 1430.56,1290.6 r45 bottom
R250 "10kΩ" R0402 6967.96,5291.89 r270 bottom
R251 "10kΩ" R0402 1460.56,1260.6 r45 bottom
R252 "10kΩ" R0402 6923.63,5291.89 r270 bottom
R253 "10kΩ" R0402 1492.61,1232.64 r45 bottom
R254 "10kΩ" R0402 6879.3,5291.89 r270 bottom
R255 "10kΩ" R0402 1527.61,1197.64 r45 bottom
R256 "10kΩ" R0402 6834.96,5291.89 r270 bottom
R257 "10kΩ" R0402 1557.61,1167.64 r45 bottom
R258 "10kΩ" R0402 6790.63,5291.89 r270 bottom
R259 "10kΩ" R0402 1590.56,1135.6 r45 bottom
R260 "10kΩ" R0402 6746.3,5291.89 r270 bottom
R261 "10kΩ" R0402 1620.56,1105.6 r45 bottom
R262 "10kΩ" R0402 6701.96,5291.89 r270 bottom
R263 "10kΩ" R0402 1652.61,1072.64 r45 bottom
R264 "10kΩ" R0402 6657.63,5291.89 r270 bottom
R265 "10kΩ" R0402 1685.56,1040.6 r45 bottom
R266 "10kΩ" R0402 6613.3,5291.89 r270 bottom
R267 "10kΩ" R0402 1717.61,1012.64 r45 bottom
R268 "10kΩ" R0402 6568.96,5291.89 r270 bottom
R269 "10kΩ" R0402 1747.61,982.64 r45 bottom
U1 "XC6206P332MR" SOT-23 5560,5805 r270 bottom
U2 "CH340C" SOP16M 5290,5510 r180 bottom
U3 "DC JW5060T_6" SOT23-6N 4465,6095 r0 bottom
U4 "LM2704MF-ADJ/NOPB" SOT-23-5_L3.0-W1.7-P0.95-LS2.8-BR 3125,5970 r270 bottom
U6 "ADG732BSUZ-REEL" TQFP-48_L7.0-W7.0-P0.50-LS9.0-TL 3015,4695 r0 bottom
U7 "ADG732BSUZ-REEL" TQFP-48_L7.0-W7.0-P0.50-LS9.0-TL 3015,3950 r0 bottom
U8 "ADG732BSUZ-REEL" TQFP-48_L7.0-W7.0-P0.50-LS9.0-TL 7235,2290 r0 bottom
U9 "ADG732BSUZ-REEL" TQFP-48_L7.0-W7.0-P0.50-LS9.0-TL 6950,4220 r180 bottom
U10 "DAC80501ZDGSR" VSSOP-10_L3.0-W3.0-P0.50-LS4.9-BL 5594.41,3178.07 r0 top
U11 "ADG732BSUZ-REEL" TQFP-48_L7.0-W7.0-P0.50-LS9.0-TL 3023.9,3425.36 r0 bottom
U12 "ADG732BSUZ-REEL" TQFP-48_L7.0-W7.0-P0.50-LS9.0-TL 2985,2240 r0 bottom
U13 "UCC27517DBVR" SOT-23-5_L3.0-W1.7-P0.95-LS2.8-BR 5680,2965 r90 top
U20 "ADG732BSUZ-REEL" TQFP-48_L7.0-W7.0-P0.50-LS9.0-TL 4570,2240 r0 bottom
U21 "ADG732BSUZ-REEL" TQFP-48_L7.0-W7.0-P0.50-LS9.0-TL 5890,2240 r0 bottom
U22 "74HC4051PW,118" TSSOP-16_L5.0-W4.4-P0.65-LS6.4-BL 5455,2750 r90 top
USB_UART1 "USB TypeC" "USB TYPE-C - 10*9" 5250,5975 r0 bottom
X1 "AFC01-S45FCA-00" FPC-SMD_AFC01-S45FCA-00 1085,5550 r270 top
X2 "AFC01-S45FCA-00" FPC-SMD_AFC01-S45FCA-00 1117.24,3843.11 r270 top
X3 "AFC01-S45FCA-00" FPC-SMD_AFC01-S45FCA-00 1100,2000 r270 top
X4 "AFC01-S45FCA-00" FPC-SMD_AFC01-S45FCA-00 4506.89,772.24 r0 top
X5 "AFC01-S45FCA-00" FPC-SMD_AFC01-S45FCA-00 5935.99,722.24 r0 top
X6 "AFC01-S45FCA-00" FPC-SMD_AFC01-S45FCA-00 7133.11,5907.76 r180 top

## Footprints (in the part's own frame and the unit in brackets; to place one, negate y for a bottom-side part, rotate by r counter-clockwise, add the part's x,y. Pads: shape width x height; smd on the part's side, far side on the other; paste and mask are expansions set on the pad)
0402 [mil]
  rect 20x20 smd: 1(-18,1) 2(18,1)
  silkscreen extent -33,-13 32,15
0603P [mil]
  rect 30x30 smd: 1(-27,0) 2(27.5,-0.06)
  Top Layer pour cut-out: -9.83,20.13 10.37,20.13 10.37,-19.66 -9.83,-19.66 -9.83,20.13
  silkscreen extent -50,-20 50,20
ARTIX7_Core [mm]
  round 2.8 hole 2.6: 0(50.184,40.184) 0_1(0,40.184) 0_2(0,0) 0_3(50.184,0)
  rect 1.7x0.35 smd: J1_1(-1.127,8.659) J1_2(3.573,8.659) J1_3(-1.127,9.459) J1_4(3.573,9.459) J1_5(-1.127,10.259) J1_6(3.573,10.259) J1_7(-1.127,11.059) J1_8(3.573,11.059) J1_9(-1.127,11.859) J1_10(3.573,11.859) J1_11(-1.127,12.659) J1_12(3.573,12.659) J1_13(-1.127,13.459) J1_14(3.573,13.459) J1_15(-1.127,14.259) J1_16(3.573,14.259) J1_17(-1.127,15.059) J1_18(3.573,15.059) J1_19(-1.127,15.859) J1_20(3.573,15.859) J1_21(-1.127,16.659) J1_22(3.573,16.659) J1_23(-1.127,17.459) J1_24(3.573,17.459) J1_25(-1.127,18.259) J1_26(3.573,18.259) J1_27(-1.127,19.059) J1_28(3.573,19.059) J1_29(-1.127,19.859) J1_30(3.573,19.859) J1_31(-1.127,20.659) J1_32(3.573,20.659) J1_33(-1.127,21.459) J1_34(3.573,21.459) J1_35(-1.127,22.259) J1_36(3.573,22.259) J1_37(-1.127,23.059) J1_38(3.573,23.059) J1_39(-1.127,23.859) J1_40(3.573,23.859) J1_41(-1.127,24.659) J1_42(3.573,24.659) J1_43(-1.127,25.459) J1_44(3.573,25.459) J1_45(-1.127,26.259) J1_46(3.573,26.259) J1_47(-1.127,27.059) J1_48(3.573,27.059) J1_49(-1.127,27.859) J1_50(3.573,27.859) J1_51(-1.127,28.659) J1_52(3.573,28.659) J1_53(-1.127,29.459) J1_54(3.573,29.459) J1_55(-1.127,30.259) J1_56(3.573,30.259) J1_57(-1.127,31.059) J1_58(3.573,31.059) J1_59(-1.127,31.859) J1_60(3.573,31.859) J3_1(46.652,8.659) J3_2(51.352,8.659) J3_3(46.652,9.459) J3_4(51.352,9.459) J3_5(46.652,10.259) J3_6(51.352,10.259) J3_7(46.652,11.059) J3_8(51.352,11.059) J3_9(46.652,11.859) J3_10(51.352,11.859) J3_11(46.652,12.659) J3_12(51.352,12.659) J3_13(46.652,13.459) J3_14(51.352,13.459) J3_15(46.652,14.259) J3_16(51.352,14.259) J3_17(46.652,15.059) J3_18(51.352,15.059) J3_19(46.652,15.859) J3_20(51.352,15.859) J3_21(46.652,16.659) J3_22(51.352,16.659) J3_23(46.652,17.459) J3_24(51.352,17.459) J3_25(46.652,18.259) J3_26(51.352,18.259) J3_27(46.652,19.059) J3_28(51.352,19.059) J3_29(46.652,19.859) J3_30(51.352,19.859) J3_31(46.652,20.659) J3_32(51.352,20.659) J3_33(46.652,21.459) J3_34(51.352,21.459) J3_35(46.652,22.259) J3_36(51.352,22.259) J3_37(46.652,23.059) J3_38(51.352,23.059) J3_39(46.652,23.859) J3_40(51.352,23.859) J3_41(46.652,24.659) J3_42(51.352,24.659) J3_43(46.652,25.459) J3_44(51.352,25.459) J3_45(46.652,26.259) J3_46(51.352,26.259) J3_47(46.652,27.059) J3_48(51.352,27.059) J3_49(46.652,27.859) J3_50(51.352,27.859) J3_51(46.652,28.659) J3_52(51.352,28.659) J3_53(46.652,29.459) J3_54(51.352,29.459) J3_55(46.652,30.259) J3_56(51.352,30.259) J3_57(46.652,31.059) J3_58(51.352,31.059) J3_59(46.652,31.859) J3_60(51.352,31.859)
  rect 0.35x1.7 smd: J2_1(40.949,-1.127) J2_2(40.949,3.573) J2_3(40.149,-1.127) J2_4(40.149,3.573) J2_5(39.349,-1.127) J2_6(39.349,3.573) J2_7(38.549,-1.127) J2_8(38.549,3.573) J2_9(37.749,-1.127) J2_10(37.749,3.573) J2_11(36.949,-1.127) J2_12(36.949,3.573) J2_13(36.149,-1.127) J2_14(36.149,3.573) J2_15(35.349,-1.127) J2_16(35.349,3.573) J2_17(34.549,-1.127) J2_18(34.549,3.573) J2_19(33.749,-1.127) J2_20(33.749,3.573) J2_21(32.948,-1.127) J2_22(32.948,3.573) J2_23(32.148,-1.127) J2_24(32.148,3.573) J2_25(31.348,-1.127) J2_26(31.348,3.573) J2_27(30.548,-1.127) J2_28(30.548,3.573) J2_29(29.748,-1.127) J2_30(29.748,3.573) J2_31(28.948,-1.127) J2_32(28.948,3.573) J2_33(28.148,-1.127) J2_34(28.148,3.573) J2_35(27.348,-1.127) J2_36(27.348,3.573) J2_37(26.548,-1.127) J2_38(26.548,3.573) J2_39(25.748,-1.127) J2_40(25.748,3.573) J2_41(24.948,-1.127) J2_42(24.948,3.573) J2_43(24.148,-1.127) J2_44(24.148,3.573) J2_45(23.348,-1.127) J2_46(23.348,3.573) J2_47(22.548,-1.127) J2_48(22.548,3.573) J2_49(21.748,-1.127) J2_50(21.748,3.573) J2_51(20.948,-1.127) J2_52(20.948,3.573) J2_53(20.148,-1.127) J2_54(20.148,3.573) J2_55(19.348,-1.127) J2_56(19.348,3.573) J2_57(18.548,-1.127) J2_58(18.548,3.573) J2_59(17.748,-1.127) J2_60(17.748,3.573) J2_61(16.948,-1.127) J2_62(16.948,3.573) J2_63(16.148,-1.127) J2_64(16.148,3.573) J2_65(15.348,-1.127) J2_66(15.348,3.573) J2_67(14.548,-1.127) J2_68(14.548,3.573) J2_69(13.748,-1.127) J2_70(13.748,3.573) J2_71(12.948,-1.127) J2_72(12.948,3.573) J2_73(12.148,-1.127) J2_74(12.148,3.573) J2_75(11.348,-1.127) J2_76(11.348,3.573) J2_77(10.548,-1.127) J2_78(10.548,3.573) J2_79(9.748,-1.127) J2_80(9.748,3.573) J4_1(40.949,36.611) J4_2(40.949,41.311) J4_3(40.149,36.611) J4_4(40.149,41.311) J4_5(39.349,36.611) J4_6(39.349,41.311) J4_7(38.549,36.611) J4_8(38.549,41.311) J4_9(37.749,36.611) J4_10(37.749,41.311) J4_11(36.949,36.611) J4_12(36.949,41.311) J4_13(36.149,36.611) J4_14(36.149,41.311) J4_15(35.349,36.611) J4_16(35.349,41.311) J4_17(34.549,36.611) J4_18(34.549,41.311) J4_19(33.749,36.611) J4_20(33.749,41.311) J4_21(32.949,36.611) J4_22(32.949,41.311) J4_23(32.149,36.611) J4_24(32.149,41.311) J4_25(31.349,36.611) J4_26(31.349,41.311) J4_27(30.549,36.611) J4_28(30.549,41.311) J4_29(29.749,36.611) J4_30(29.749,41.311) J4_31(28.949,36.611) J4_32(28.949,41.311) J4_33(28.149,36.611) J4_34(28.149,41.311) J4_35(27.349,36.611) J4_36(27.349,41.311) J4_37(26.549,36.611) J4_38(26.549,41.311) J4_39(25.749,36.611) J4_40(25.749,41.311) J4_41(24.949,36.611) J4_42(24.949,41.311) J4_43(24.149,36.611) J4_44(24.149,41.311) J4_45(23.349,36.611) J4_46(23.349,41.311) J4_47(22.549,36.611) J4_48(22.549,41.311) J4_49(21.749,36.611) J4_50(21.749,41.311) J4_51(20.949,36.611) J4_52(20.949,41.311) J4_53(20.149,36.611) J4_54(20.149,41.311) J4_55(19.349,36.611) J4_56(19.349,41.311) J4_57(18.549,36.611) J4_58(18.549,41.311) J4_59(17.749,36.611) J4_60(17.749,41.311) J4_61(16.948,36.611) J4_62(16.948,41.311) J4_63(16.148,36.611) J4_64(16.148,41.311) J4_65(15.348,36.611) J4_66(15.348,41.311) J4_67(14.548,36.611) J4_68(14.548,41.311) J4_69(13.748,36.611) J4_70(13.748,41.311) J4_71(12.948,36.611) J4_72(12.948,41.311) J4_73(12.148,36.611) J4_74(12.148,41.311) J4_75(11.348,36.611) J4_76(11.348,41.311) J4_77(10.548,36.611) J4_78(10.548,41.311) J4_79(9.748,36.611) J4_80(9.748,41.311)
  round 1.3 / inner round 1.524 / far side round 1.3 hole 1.3: ""(1.224,34.36) ""(7.248,38.961) ""(7.248,1.223) ""(49.002,34.36)
  round 0.9 hole 0.9: ""(1.224,6.16) ""(43.448,1.223) ""(49.002,6.16)
  round 0.9 / inner round 1.524 / far side round 0.9 hole 0.9: ""(43.448,38.961)
  silkscreen extent -2.41,-2.41 52.59,46.61
BTN8.5*8.5 [mm]
  rect 1.5x1.5 hole 0.8: 1(0,0)
  round 1.5 hole 0.8: 2(0,-2.54) 3(0,-5.08) 4(5.4,-5.08) 5(5.4,-2.54) 6(5.4,0)
  silkscreen extent -1.55,-6.79 6.95,1.71
"C 0603_M" [mil] "无极性贴片电容                                淘宝ID:黄晶宝石"
  rect 40x30 smd: 1(-36.5,0) 2(36.5,0)
  silkscreen extent -68,-26 68,26, body extent -31,-16 31,16, height 32
"CD S(2012)" [mm] "长2.0mm，宽1.25mm，厚1.2mm               淘宝ID:黄晶宝石"
  rect 1.1x1.3 smd: 1(-1.1,0) 2(1.1,0)
  silkscreen extent -2.03,-0.89 1.91,0.89, body extent -1,-0.6 1,0.6, height 1.2
"CM D(6.3*5.4)" [mm]
  rect 3.2x1.5 smd: 1(2.7,0) 2(-2.7,0)
  silkscreen extent -3.3,-3.3 3.3,3.3
DC10B [mil]
  oval 80x180 hole 50 slot 110 at 90 deg: 1(0,0)
  oval 80x180 hole 50 slot 120 at 90 deg: 2(244.09,0)
  oval 180x80 hole 50 slot 110 at 0 deg: 3(122.05,196.85)
  silkscreen extent -46,-180 557,170
DIO-SMD_L2.0-W1.9-LS3.8-RD [mm]
  rect 2.7x2.2 smd: 1(-1.185,-0.001)
  rect 1.27x0.77 smd: 2(1.185,0.001)
  silkscreen extent -1.91,-1.3 0.39,1.3
FPC-SMD_AFC01-S45FCA-00 [mm]
  rect 0.3x1.3 smd: 1(-11,1.34) 2(-10.5,1.338) 3(-10,1.34) 4(-9.5,1.34) 5(-9,1.34) 6(-8.5,1.34) 7(-8,1.34) 8(-7.5,1.34) 9(-7,1.34) 10(-6.5,1.34) 11(-6,1.34) 12(-5.5,1.34) 13(-5,1.34) 14(-4.5,1.34) 15(-4,1.34) 16(-3.5,1.34) 17(-3,1.34) 18(-2.5,1.34) 19(-2,1.34) 20(-1.5,1.34) 21(-1,1.34) 22(-0.5,1.34) 23(0,1.34) 24(0.5,1.34) 25(1,1.34) 26(1.5,1.34) 27(2,1.34) 28(2.5,1.34) 29(3,1.34) 30(3.5,1.34) 31(4,1.34) 32(4.5,1.34) 33(5,1.34) 34(5.5,1.34) 35(6,1.34) 36(6.5,1.34) 37(7,1.34) 38(7.5,1.34) 39(8,1.34) 40(8.5,1.34) 41(9,1.34) 42(9.5,1.34) 43(10,1.34) 44(10.5,1.34) 45(11,1.34)
  rect 2x1.6 smd: 46(12.7,-1.34) 47(-12.7,-1.34)
  silkscreen extent -13.46,-4.36 13.46,1.61
HDR1X2 [mm] "Connector; Header; 2 Position"
  rect 1.5x1.5 hole 0.9: 1(0,0)
  round 1.5 hole 0.9: 2(2.54,0)
  silkscreen extent -1.27,-1.27 3.81,1.27
HDR-IDC-SMD_10PIN-V-ROW2-COL5-PITCH2.00 [mm]
  rect 0.8x2 smd: 1(-4,-3.3) 2(-4,3.3) 3(-2,-3.3) 4(-2,3.3) 5(0,-3.3) 6(0,3.3) 7(2,-3.3) 8(2,3.3) 9(4,-3.3) 10(4,3.3)
  silkscreen extent -8.83,-3.56 8.83,2.79
HDR-TH_6P-P2.54-V-M-R2-C3-S2.54 [mm]
  rect 1.7x1.7 hole 1.1: 1(-2.54,-1.27)
  round 1.7 hole 1.1: 2(-2.54,1.27) 3(0,-1.27) 4(0,1.27) 5(2.54,-1.27) 6(2.54,1.27)
  silkscreen extent -4.04,-2.54 4.04,2.54
HDR-TH_16P-P1.27-V-M [mm]
  rect 1x1 hole 0.7: 1(-9.525,0)
  round 1 hole 0.7: 2(-8.255,0) 3(-6.985,0) 4(-5.715,0) 5(-4.445,0) 6(-3.175,0) 7(-1.905,0) 8(-0.635,0) 9(0.635,0) 10(1.905,0) 11(3.175,0) 12(4.445,0) 13(5.715,0) 14(6.985,0) 15(8.255,0) 16(9.525,0)
  silkscreen extent -10.24,-1.08 10.24,1.08
L-SMD-0420 [mm]
  rrect0% 2x2 smd: 1(-2,0) 2(2,0)
  silkscreen extent -2.39,-2.16 2.36,2.17
NR6028 [mm] "6.0mm*6.0mm*2.8mm(长*宽*高）"
  rect 1.7x5.7 smd: 1(-2.25,0) 2(2.25,0)
  silkscreen extent -3.3,-3.05 3.3,3.05, body extent -3,-3 3,3, height 2.9
R0402 [mm]
  rect 0.566x0.54 smd paste-100 mask+0.051: 1(-0.433,0) 2(0.433,0)
  silkscreen extent -0.94,-0.5 0.94,0.5
"R 0603_M" [mil] "1/10W贴片电阻                             淘宝ID:黄晶宝石"
  rect 40x31.5 smd: 1(-36.5,0) 2(36.5,0)
  silkscreen extent -68,-26 68,26, body extent -31,-16 31,16, height 16
SMA [mm]
  rect 2.2x1.75 smd: 1(-2.3,0) 2(2.3,0)
  silkscreen extent -2.7,-1.52 3.56,1.52
SOD-123 [mil] "2.7x1.6X1.1mm（长宽高，不包括引脚） 淘宝ID:黄晶宝石"
  rect 55x50 smd: 1(-67.5,0)
  oct 55x50 smd: 2(67.5,0)
  silkscreen extent -108,-35 112,35, body extent -73,-31 73,31, height 48
SOP16M [mm]
  rect 0.6x2.2 smd: 1(-4.445,-2.6) 2(-3.175,-2.6) 3(-1.905,-2.6) 4(-0.635,-2.6) 5(0.635,-2.6) 6(1.905,-2.6) 7(3.175,-2.6) 8(4.445,-2.6) 9(4.445,2.6) 10(3.175,2.6) 11(1.905,2.6) 12(0.635,2.6) 13(-0.635,2.6) 14(-1.905,2.6) 15(-3.175,2.6) 16(-4.445,2.6)
  silkscreen extent -5.42,-2.72 5,1.1
SOT23-6N [mm]
  rect 1x0.55 smd: 1(1.3,-0.95) 2(1.3,0) 3(1.3,0.95) 4(-1.3,0.95) 5(-1.3,0) 6(-1.3,-0.95)
  silkscreen extent -0.51,-1.78 1.78,1.55
SOT-23 [mil]
  rect 55x40 smd: 1(-37.3,38.83) 2(-37.3,-35.98) 3(41.09,1.43)
  silkscreen extent 6,-57 51,58
SOT-23-5_L3.0-W1.7-P0.95-LS2.8-BR [mm]
  rect 1x0.6 smd: 1(1.3,-0.95) 2(1.3,0) 3(1.3,0.95) 4(-1.3,0.95) 5(-1.3,-0.95)
  silkscreen extent -0.9,-1.78 1.65,1.55, body extent -0.89,-1.52 0.89,1.52, height 0.76
TQFP-48_L7.0-W7.0-P0.50-LS9.0-TL [mm]
  oval 1.8x0.28 smd: 1(-4.2,2.75) 2(-4.2,2.25) 3(-4.2,1.75) 4(-4.2,1.25) 5(-4.2,0.75) 6(-4.2,0.25) 7(-4.2,-0.25) 8(-4.2,-0.75) 9(-4.2,-1.25) 10(-4.2,-1.75) 11(-4.2,-2.25) 12(-4.2,-2.75) 25(4.2,-2.75) 26(4.2,-2.25) 27(4.2,-1.75) 28(4.2,-1.25) 29(4.2,-0.75) 30(4.2,-0.25) 31(4.2,0.25) 32(4.2,0.75) 33(4.2,1.25) 34(4.2,1.75) 35(4.2,2.25) 36(4.2,2.75)
  oval 0.28x1.8 smd: 13(-2.75,-4.2) 14(-2.25,-4.2) 15(-1.75,-4.2) 16(-1.25,-4.2) 17(-0.75,-4.2) 18(-0.25,-4.2) 19(0.25,-4.2) 20(0.75,-4.2) 21(1.25,-4.2) 22(1.75,-4.2) 23(2.25,-4.2) 24(2.75,-4.2) 37(2.75,4.2) 38(2.25,4.2) 39(1.75,4.2) 40(1.25,4.2) 41(0.75,4.2) 42(0.25,4.2) 43(-0.25,4.2) 44(-0.75,4.2) 45(-1.25,4.2) 46(-1.75,4.2) 47(-2.25,4.2) 48(-2.75,4.2)
  silkscreen extent -4.45,-2.75 2.75,3.65
TSSOP-16_L5.0-W4.4-P0.65-LS6.4-BL [mil]
  oval 13.5x68.17 smd: 1(-89.57,-112.82) 2(-63.98,-112.82) 3(-38.39,-112.82) 4(-12.79,-112.82) 5(12.8,-112.82) 6(38.39,-112.82) 7(63.98,-112.82) 8(89.57,-112.82) 9(89.57,112.82) 10(63.98,112.82) 11(38.39,112.82) 12(12.8,112.82) 13(-12.79,112.82) 14(-38.39,112.82) 15(-63.98,112.82) 16(-89.57,112.82)
  silkscreen extent -120,-119 101,70
"USB TYPE-C - 10*9" [mm]
  rect 0.6x1.3 smd mask+0.064: 1(-3.2,2.462) 2(-2.4,2.462) 11(2.4,2.462) 12(3.2,2.462)
  rect 0.3x1.3 smd mask+0.064: 3(-1.75,2.462) 4(-1.25,2.462) 5(-0.75,2.462) 6(-0.25,2.463) 7(0.25,2.463) 8(0.75,2.462) 9(1.25,2.462) 10(1.75,2.462)
  oval 1x2.1 hole 0.6 slot 1.6 at 90 deg: SH1(-4.32,1.718) SH3(4.32,1.717)
  oval 1x1.6 hole 0.6 slot 1.2 at 90 deg: SH2(-4.32,-2.462) SH4(4.32,-2.462)
  rect 1x1 smd mask+0: SH2(-1.524,-4.064) SH2(-1.524,-2.54) SH2(-1.524,-1.016) SH2(0,-4.064) SH2(0,-2.54) SH2(0,-1.016) SH2(1.524,-4.064)
  rect 1x1 smd paste+0 mask+0: SH2(1.524,-2.54) SH2(1.524,-1.016)
  round 0.65 hole 0.65 unplated mask+0: ""(-2.89,1.218) ""(2.89,1.218)
  silkscreen extent -4.34,-5.07 4.32,0.37
VSSOP-10_L3.0-W3.0-P0.50-LS4.9-BL [mm]
  rect 0.3x1.3 smd paste+0 mask+0.015: 1(-1,-2.35) 2(-0.5,-2.35) 3(0,-2.35) 4(0.5,-2.35) 5(1,-2.35)
  rect 0.3x1.3 smd: 6(1,2.35) 7(0.5,2.35) 8(0,2.35) 9(-0.5,2.35) 10(-1,2.35)
  silkscreen extent -1.62,-2.08 1.52,1.54

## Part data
Battery1: "Header, 2-Pin"
C1 C2 C3 C4 C5 C6 C7 C8 C10 C11 C12 C13 C17 C20 C21 C22 C23 C24 C25 C26 C27 C29 C30 C31: library part C
C9: library part C-CM, "贴片电解电容"
C14 C15 C16: library part C, "无极性贴片电容"
D1: library part SS14, "肖特基二极管"
D2: Average Rectified Current (Io)=1A, Forward Voltage (Vf@If)=380mV@1A, JLCPCB Part Class="Extended Part", LCSC Part Name="电压:30V 电流:1A", Manufacturer=onsemi(安森美), Reverse Leakage Current (Ir)=410uA@30V, Reverse Voltage (Vr)=30V
D3 D4: library part SMBJ, "TVS"
DC_IN1: library part P-DC, "低压电源接口"
E1: library part CT, "贴片钽电容"
H1: Color=黑色, Current Rating (Max)=-, JLCPCB Part Class="Extended Part", LCSC Part Name="间距:2.54mm 2x3P 直插 方针", Manufacturer=XFCN(兴飞), Operating Temperature Range=-40℃~+105℃
H2 H3 H4 H5 H6 H7 H8 H9 H10 H11 H12 H13 H14 H15 H16 H17: Color=黑色, Current Rating=1A, LCSC Part Name="1x16P 间距:1.27mm 方针 直插", Manufacturer=Bossie(博锡), Operating Temperature=-40℃~+105℃, Voltage Rating (Max)=-
L1: library part L-CDRH, "功率屏蔽电感"
L2: library part L, "小功率贴片电感"
M1: library part "Artix7 Core connector", "达芬奇pro A7核心板连接器"
R1 R2 R3 R4 R7 R8 R9 R10: library part R
R5 R6 R11 R12 R138: library part R, "贴片电阻"
R13 R14 R15 R16 R17 R18 R19 R20 R21 R22 R23 R24 R25 R26 R27 R28 R29 R30 R31 R32 R33 R34 R35 R36 R37 R38 R39 R40 R41 R42 R43 R44 R45 R46 R47 R48 R49 R50 R51 R52 R53 R54 R55 R56 R57 R58 R59 R60 R61 R62 R63 R64 R65 R66 R67 R68 R69 R70 R71 R72 R73 R74 R75 R76 R77 R78 R79 R80 R81 R82 R83 R84 R85 R86 R87 R88 R89 R90 R91 R92 R93 R94 R95 R96 R97 R98 R99 R100 R101 R102 R103 R104 R105 R106 R107 R108 R109 R110 R111 R112 R113 R114 R115 R116 R117 R118 R119 R120 R121 R122 R123 R124 R125 R126 R127 R128 R129 R130 R131 R132 R133 R134 R135 R136 R137 R139 R140 R141 R142 R143 R144 R145 R146 R147 R148 R149 R150 R151 R152 R153 R154 R155 R156 R157 R158 R159 R160 R161 R162 R163 R164 R165 R166 R167 R168 R169 R170 R171 R172 R173 R174 R175 R176 R177 R178 R179 R180 R181 R182 R183 R184 R185 R186 R187 R188 R189 R190 R191 R192 R193 R194 R195 R196 R197 R198 R199 R200 R201 R202 R203 R204 R205 R206 R207 R208 R209 R210 R211 R212 R213 R214 R215 R216 R217 R218 R219 R220 R221 R222 R223 R224 R225 R226 R227 R228 R229 R230 R231 R232 R233 R234 R235 R236 R237 R238 R239 R240 R241 R242 R243 R244 R245 R246 R247 R248 R249 R250 R251 R252 R253 R254 R255 R256 R257 R258 R259 R260 R261 R262 R263 R264 R265 R266 R267 R268 R269: library part 0402WGF1002TCE, JLCPCB Part Class="Basic Part", LCSC Part Name="10kΩ ±1% 62.5mW 厚膜电阻", Manufacturer=UNI-ROYAL(厚声), Operating Temperature=-55℃~+155℃, Power(Watts)=62.5mW, Temperature Coefficient=±100ppm/℃, Tolerance=±1%, Voltage-Supply(Max)=50V
U1: library part XC6206P332MR_C347376, BOM_LCSC Assembly=Yes, BOM_Manufacturer="Youtai Semiconductor Co., Ltd."
U2: library part CH340G, "USB2UART"
U3: "DC降压芯片"
U4: Input Voltage=2.2V~7V, JLCPCB Part Class="Extended Part", Manufacturer=TI(德州仪器), Operating Temperature=-40℃~+85℃@(TA), Output Current (Max)=550mA, Output Voltage=20V, Switching Frequency=-
U6 U7 U8 U9 U11 U12 U20 U21: JLCPCB Part Class="Extended Part", LCSC Part Name="16-/32-通道, 4 Ω, +1.8 V 至 +5.5 V 和 ±2.5 V 模拟多路复用器", Manufacturer=ADI(亚德诺), Operating Temperature=-40℃~+125℃, Voltage - Supply=1.8V~5.5V
U10: JLCPCB Part Class="Extended Part", LCSC Part Name=具有精密内部基准的DACx0501位电压输出DAC, Manufacturer=TI(德州仪器), Operating Temperature=-40℃~+125℃, Power-On Reset=内置, Supply Current (Iq)=15uA, Voltage - Supply=2.7V~5.5V, Voltage Reference Drift=5ppm/℃
U13: Current - Output High(IOH)=4A, JLCPCB Part Class="Extended Part", LCSC Part Name=UCC2751x单通道、高速、低侧栅极驱动器, Manufacturer=TI(德州仪器), Operating Temperature=-40℃~+140℃, Voltage - Supply=4.5V~18V
U22: JLCPCB Part Class="Extended Part", LCSC Part Name=8通道模拟多路复用器/解复用器, Manufacturer=Nexperia(安世), Operating Temperature=-40℃~+125℃, Voltage - Supply=2V~10V
USB_UART1: library part "USB Type-C", "12P TypeC 母座"
X1 X2 X3 X4 X5 X6: JLCPCB Part Class="Extended Part", LCSC Part Name="间距:0.5mm P数:45P 翻盖式 下接", Manufacturer=JS(钜硕电子), Operating Temperature Range=-

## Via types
v1: diameter 18, hole 12, Top Layer to Bottom Layer, 429 vias

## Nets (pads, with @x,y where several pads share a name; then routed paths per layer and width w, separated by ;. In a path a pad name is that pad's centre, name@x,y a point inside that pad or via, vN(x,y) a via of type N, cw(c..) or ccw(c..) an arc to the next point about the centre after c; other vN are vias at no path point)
+3.3V: D3.2 JTAG1.4
+5V: C20.1 C21.1 C22.1 C23.1 C24.2 C25.2 C26.1 C27.1 C29.1 C30.1 C31.1 D4.2 E1.1 K1.2 M1.J2_1 M1.J2_2 M1.J2_3 M1.J2_4 M1.J2_5 M1.J2_6 M1.J2_7 M1.J2_8 R138.2 U6.13 U6.14 U7.13 U7.14 U8.13 U8.14 U9.13 U9.14 U10.1 U11.13 U11.14 U12.13 U12.14 U13.1 U20.13 U20.14 U21.13 U21.14 U22.16 | length 53.5
  Top Layer w15: R138.2@5791.5,3200 v1(5791.5,3253.5)
  other v1: 2760,2390 5665,2390 4345,2405 7010,2440 5265,2640 5590,2975 5800,3050 2855,3650 7180,4060 2865,4180 2855,4910 4440,5120 4485,5120 4530,5120
A0: M1.J4_59 U6.15 U7.15 U8.15 U9.15 U11.15 U12.15 U20.15 U21.15 | length 15596.8
  Top Layer w10: v1(2921.16,3995) 2921.16,3952.78 3004.94,3869 3032.94,3869 3033.31,3868.63 3716.37,3868.63 3721.53,3863.47 3868.47,3863.47 v1(3870,3865) ; v1(2921.16,4780) 2921.16,4743.84 3029.03,4635.97 3844.03,4635.97 3870,4610 v1(3905,4610) ; v1(2938.37,3660) v1(2938.37,3846.63) ; v1(3765,3174) 3765,2850 3825,2790 4235,2790 4475,2550 v1(4475,2520) 5775,2520 v1(5800,2495) 5955,2495 5985,2525 v1(6695,2525) 6695.28,2525.28 6695.28,2759.72 v1(6695,2760) ; v1(4355,3750) 4355,3785 4430,3860 v1(5110,3860) 5358.12,3860 5363.98,3854.14 v1(5363.98,3820) 5363.21,3819.23 5363.21,3730.06 M1.J4_59@5362.44,3729.29 M1.J4_59@5360.55,3727.4
  Bottom Layer w10: U12.15@2916.1,2405.36 2916.1,2457.56 3632.54,3174 v1(3765,3174) ; v1(2921.16,4780) 2921.16,4785.94 2946.1,4810.88 U6.15@2946.1,4860.36 ; v1(2938.37,3660) 2938.37,3654.06 2955,3637.43 U11.15@2955,3590.71 ; v1(2938.37,3846.63) 2938.37,3912.21 2921.16,3929.42 v1(2921.16,3995) 2921.16,4026.16 2946.1,4051.1 U7.15@2946.1,4115.36 ; v1@3768.7,3174 3768.7,3175.53 3840.53,3175.53 3865,3200 3865,3675 3940,3750 v1(4355,3750) ; v1(3870,3865) 4108.7,3865 4115.2,3858.5 4148.82,3858.5 4152.32,3855 5102.84,3855 5107.84,3860 v1(5110,3860) ; v1(3905,4610) 5205,4610 5315,4500 5415,4500 5415,4095 5363.98,4043.98 v1(5363.98,3820) ; v1(4475,2520) 4501.1,2493.9 U20.15@4501.1,2405.36 ; v1(5800,2495) 5821.1,2473.9 U21.15@5821.1,2405.36 ; v1(6695,2525) 7136.89,2525 7166.1,2495.79 U8.15@7166.1,2455.36 ; v1(6695,2760) 6695,3650 7018.9,3973.9 U9.15@7018.9,4054.64
A1: M1.J4_61 U6.16 U7.16 U8.16 U9.16 U11.16 U12.16 U20.16 U21.16 | length 15610.3
  Top Layer w10: v1(2949.16,3995) 2949.16,3950.84 3015,3885 3433.92,3885 3443.92,3895 v1(3870,3895) ; v1(2949.16,4780) 2949.16,4758.9 3056.09,4651.97 3867.12,4651.97 3874.09,4645 v1(3905,4645) ; v1(2966.37,3660) v1(2966.37,3846.37) ; v1(3795,3150) 3795,2865 3850.31,2809.69 4260.31,2809.69 4498.47,2571.53 4498.47,2551.53 v1(4500,2550) 4697.85,2550 4711.85,2536 5822.41,2536 5830.94,2527.47 5830.94,2521.53 v1(5832.47,2520) 5833.33,2519.14 5904.3,2519.14 5940.15,2555 v1(6660,2555) v1(6660,2760) ; v1(4325,3725) 4325,3797.5 4417.5,3890 v1(5110,3890) 5389.66,3890 5395.52,3884.14 v1(5395.52,3820) 5394.75,3819.23 5394.75,3730.06 M1.J4_61@5393.98,3729.29
  Bottom Layer w10: U12.16@2935.79,2405.36 2935.79,2454.62 3631.17,3150 v1(3795,3150) 3796,3149 3857.69,3149 3910,3201.31 3910,3670 3965,3725 v1(4325,3725) ; v1(2949.16,4780) 2949.16,4785.94 2965.79,4802.57 U6.16@2965.79,4860.36 ; U7.16@2965.79,4115.36 2965.79,4045.79 2949.16,4029.16 v1(2949.16,3995) 2949.16,3930.84 2966.37,3913.63 v1(2966.37,3846.37) ; v1(2966.37,3660) 2966.37,3654.06 2974.69,3645.74 U11.16@2974.69,3590.71 ; v1(3870,3895) 5102.84,3895 5107.84,3890 v1(5110,3890) ; v1(3905,4645) 5205,4645 5315,4535 5415,4535 5450,4500 5450,4095 5395.52,4040.52 v1(5395.52,3820) ; v1(4500,2550) 4520.79,2529.21 U20.16@4520.79,2405.36 ; v1(5832.47,2520) 5832.47,2514.06 5840.79,2505.74 U21.16@5840.79,2405.36 ; v1(6660,2555) 6928.34,2555 6933.34,2560 7124.52,2560 7185.79,2498.73 U8.16@7185.79,2455.36 ; v1(6660,2760) 6660,3645 6999.21,3984.21 U9.16@6999.21,4054.64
